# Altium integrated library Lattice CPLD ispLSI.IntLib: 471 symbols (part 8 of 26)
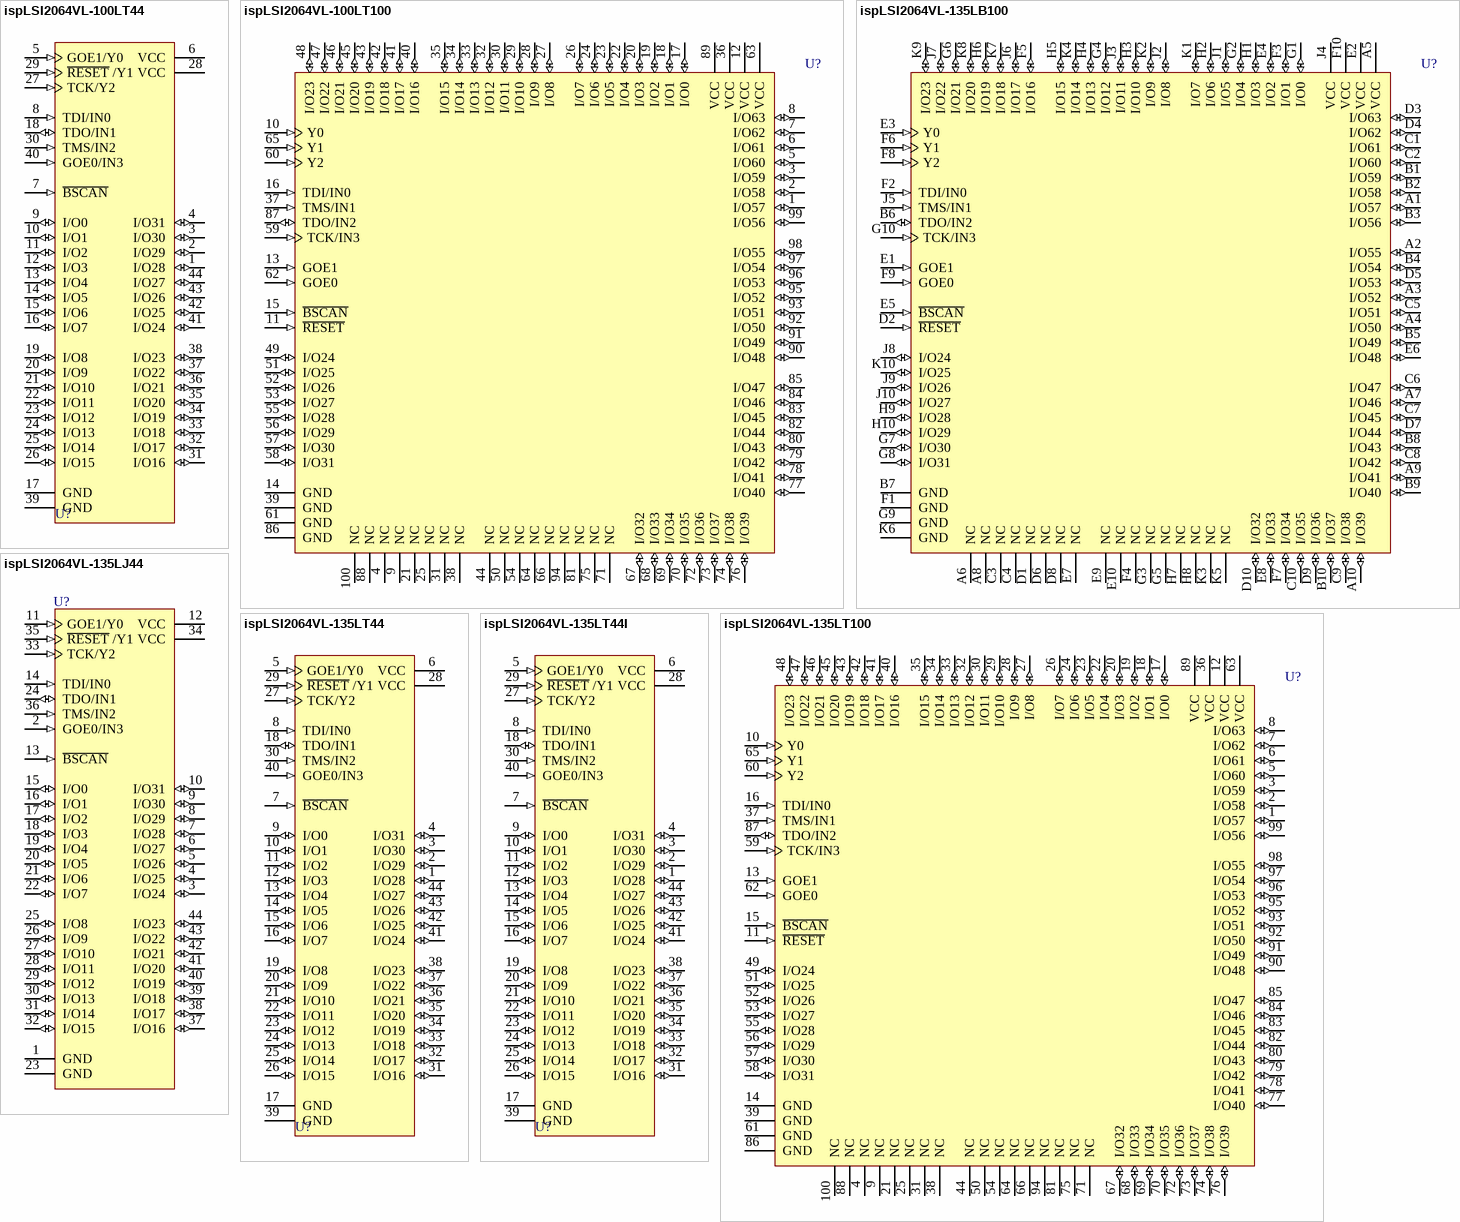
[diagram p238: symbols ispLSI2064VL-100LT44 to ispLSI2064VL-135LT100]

## ispLSI2064VL-100LT44
designator U?
2.5V In-System Programmable SuperFAST High Density PLD
footprint TQFP44_N (Thin QFP, 44-Leads, Body 10x10mm, Pitch 0.8mm, IPC Medium Density)
footprint TQFP44_L (Thin QFP, 44-Leads, Body 10x10mm, Pitch 0.8mm, IPC High Density)
footprint TQFP44_M (Thin QFP, 44-Leads, Body 10x10mm, Pitch 0.8mm, IPC Low Density)
3D model 2064VL-TQFP44 (44-Pin Thin Quad Flat Pack 0.8 mm Pitch)
pins: 1 I/O28 (io), 2 I/O29 (io), 3 I/O30 (io), 4 I/O31 (io), 5 GOE1/Y0 (in), 6 VCC (power), 7 ~{BSCAN} (in), 8 TDI/IN0 (in), 9 I/O0 (io), 10 I/O1 (io), 11 I/O2 (io), 12 I/O3 (io), 13 I/O4 (io), 14 I/O5 (io), 15 I/O6 (io), 16 I/O7 (io), 17 GND (power), 18 TDO/IN1 (io), 19 I/O8 (io), 20 I/O9 (io), 21 I/O10 (io), 22 I/O11 (io), 23 I/O12 (io), 24 I/O13 (io), 25 I/O14 (io), 26 I/O15 (io), 27 TCK/Y2 (in), 28 VCC (power), 29 ~{RESET} /Y1 (in), 30 TMS/IN2 (in), 31 I/O16 (io), 32 I/O17 (io), 33 I/O18 (io), 34 I/O19 (io), 35 I/O20 (io), 36 I/O21 (io), 37 I/O22 (io), 38 I/O23 (io), 39 GND (power), 40 GOE0/IN3 (in), 41 I/O24 (io), 42 I/O25 (io), 43 I/O26 (io), 44 I/O27 (io)

## ispLSI2064VL-100LT100
designator U?
2.5V In-System Programmable SuperFAST High Density PLD
footprint TQFP100_N (Thin QFP, 100-Leads, Body 14x14mm, Pitch 0.5mm, IPC Medium Density)
footprint TQFP100_L (Thin QFP, 100-Leads, Body 14x14mm, Pitch 0.5mm, IPC High Density)
footprint TQFP100_M (Thin QFP, 100-Leads, Body 14x14mm, Pitch 0.5mm, IPC Low Density)
3D model 2064VL-TQFP100 (100-Pin Thin Quad Flat Pack (TQFP100))
pins: 1 I/O57 (io), 2 I/O58 (io), 3 I/O59 (io), 4 NC, 5 I/O60 (io), 6 I/O61 (io), 7 I/O62 (io), 8 I/O63 (io), 9 NC, 10 Y0 (in), 11 ~{RESET} (in), 12 VCC (power), 13 GOE1 (in), 14 GND (power), 15 ~{BSCAN} (in), 16 TDI/IN0 (in), 17 I/O0 (io), 18 I/O1 (io), 19 I/O2 (io), 20 I/O3 (io), 21 NC, 22 I/O4 (io), 23 I/O5 (io), 24 I/O6 (io), 25 NC, 26 I/O7 (io), 27 I/O8 (io), 28 I/O9 (io), 29 I/O10 (io), 30 I/O11 (io), 31 NC, 32 I/O12 (io), 33 I/O13 (io), 34 I/O14 (io), 35 I/O15 (io), 36 VCC (power), 37 TMS/IN1 (in), 38 NC, 39 GND (power), 40 I/O16 (io), 41 I/O17 (io), 42 I/O18 (io), 43 I/O19 (io), 44 NC, 45 I/O20 (io), 46 I/O21 (io), 47 I/O22 (io), 48 I/O23 (io), 49 I/O24 (io), 50 NC, 51 I/O25 (io), 52 I/O26 (io), 53 I/O27 (io), 54 NC, 55 I/O28 (io), 56 I/O29 (io), 57 I/O30 (io), 58 I/O31 (io), 59 TCK/IN3 (in), 60 Y2 (in), 61 GND (power), 62 GOE0 (in), 63 VCC (power), 64 NC, 65 Y1 (in), 66 NC, 67 I/O32 (io), 68 I/O33 (io), 69 I/O34 (io), 70 I/O35 (io), 71 NC, 72 I/O36 (io), 73 I/O37 (io), 74 I/O38 (io), 75 NC, 76 I/O39 (io), 77 I/O40 (io), 78 I/O41 (io), 79 I/O42 (io), 80 I/O43 (io), 81 NC, 82 I/O44 (io), 83 I/O45 (io), 84 I/O46 (io), 85 I/O47 (io), 86 GND (power), 87 TDO/IN2 (io), 88 NC, 89 VCC (power), 90 I/O48 (io), 91 I/O49 (io), 92 I/O50 (io), 93 I/O51 (io), 94 NC, 95 I/O52 (io), 96 I/O53 (io), 97 I/O54 (io), 98 I/O55 (io), 99 I/O56 (io), 100 NC

## ispLSI2064VL-135LB100
designator U?
2.5V In-System Programmable SuperFAST High Density PLD
footprint caBGA100 (BGA, 100-Leads, Body 10x10mm, Pitch 0.8mm)
3D model 2064VL-caBGA100 (100-Ball Chip Array Ball Grid Array (caBGA100))
pins: A1 I/O57 (io), A2 I/O55 (io), A3 I/O52 (io), A4 I/O50 (io), A5 VCC (power), A6 NC, A7 I/O46 (io), A8 NC, A9 I/O41 (io), A10 I/O39 (io), B1 I/O59 (io), B2 I/O58 (io), B3 I/O56 (io), B4 I/O54 (io), B5 I/O49 (io), B6 TDO/IN2 (io), B7 GND (power), B8 I/O43 (io), B9 I/O40 (io), B10 I/O37 (io), C1 I/O61 (io), C2 I/O60 (io), C3 NC, C4 NC, C5 I/O51 (io), C6 I/O47 (io), C7 I/O45 (io), C8 I/O42 (io), C9 I/O38 (io), C10 I/O35 (io), D1 NC, D2 ~{RESET} (in), D3 I/O63 (io), D4 I/O62 (io), D5 I/O53 (io), D6 NC, D7 I/O44 (io), D8 NC, D9 I/O36 (io), D10 I/O32 (io), E1 GOE1 (in), E2 VCC (power), E3 Y0 (in), E4 I/O2 (io), E5 ~{BSCAN} (in), E6 I/O48 (io), E7 NC, E8 I/O33 (io), E9 NC, E10 NC, F1 GND (power), F2 TDI/IN0 (in), F3 I/O1 (io), F4 NC, F5 I/O16 (io), F6 Y1 (in), F7 I/O34 (io), F8 Y2 (in), F9 GOE0 (in), F10 VCC (power), G1 I/O0 (io), G2 I/O4 (io), G3 NC, G4 I/O12 (io), G5 NC, G6 I/O21 (io), G7 I/O30 (io), G8 I/O31 (io), G9 GND (power), G10 TCK/IN3 (in), H1 I/O3 (io), H2 I/O6 (io), H3 I/O10 (io), H4 I/O13 (io), H5 I/O15 (io), H6 I/O19 (io), H7 NC, H8 NC, H9 I/O28 (io), H10 I/O29 (io), J1 I/O5 (io), J2 I/O8 (io), J3 I/O11 (io), J4 VCC (power), J5 TMS/IN1 (in), J6 I/O17 (io), J7 I/O22 (io), J8 I/O24 (io), J9 I/O26 (io), J10 I/O27 (io), K1 I/O7 (io), K2 I/O9 (io), K3 NC, K4 I/O14 (io), K5 NC, K6 GND (power), K7 I/O18 (io), K8 I/O20 (io), K9 I/O23 (io), K10 I/O25 (io)

## ispLSI2064VL-135LJ44
designator U?
2.5V In-System Programmable SuperFAST High Density PLD
footprint PLCC44_N (Leaded Chip Carrier, 44-Leads, Body 16.6x16.6mm, Pitch 1.27mm, IPC Medium Density)
footprint PLCC44_L (Leaded Chip Carrier, 44-Leads, Body 16.6x16.6mm, Pitch 1.27mm, IPC High Density)
footprint PLCC44_M (Leaded Chip Carrier, 44-Leads, Body 16.6x16.6mm, Pitch 1.27mm, IPC Low Density)
3D model 2064VL-PLCC44 (44-Pin Leaded Chip Carrier 1.27 mm Pitch)
pins: 1 GND (power), 2 GOE0/IN3 (in), 3 I/O24 (io), 4 I/O25 (io), 5 I/O26 (io), 6 I/O27 (io), 7 I/O28 (io), 8 I/O29 (io), 9 I/O30 (io), 10 I/O31 (io), 11 GOE1/Y0 (in), 12 VCC (power), 13 ~{BSCAN} (in), 14 TDI/IN0 (in), 15 I/O0 (io), 16 I/O1 (io), 17 I/O2 (io), 18 I/O3 (io), 19 I/O4 (io), 20 I/O5 (io), 21 I/O6 (io), 22 I/O7 (io), 23 GND (power), 24 TDO/IN1 (io), 25 I/O8 (io), 26 I/O9 (io), 27 I/O10 (io), 28 I/O11 (io), 29 I/O12 (io), 30 I/O13 (io), 31 I/O14 (io), 32 I/O15 (io), 33 TCK/Y2 (in), 34 VCC (power), 35 ~{RESET} /Y1 (in), 36 TMS/IN2 (in), 37 I/O16 (io), 38 I/O17 (io), 39 I/O18 (io), 40 I/O19 (io), 41 I/O20 (io), 42 I/O21 (io), 43 I/O22 (io), 44 I/O23 (io)

## ispLSI2064VL-135LT44
designator U?
2.5V In-System Programmable SuperFAST High Density PLD
footprint TQFP44_N (Thin QFP, 44-Leads, Body 10x10mm, Pitch 0.8mm, IPC Medium Density)
footprint TQFP44_L (Thin QFP, 44-Leads, Body 10x10mm, Pitch 0.8mm, IPC High Density)
footprint TQFP44_M (Thin QFP, 44-Leads, Body 10x10mm, Pitch 0.8mm, IPC Low Density)
3D model 2064VL-TQFP44 (44-Pin Thin Quad Flat Pack 0.8 mm Pitch)
pins: 1 I/O28 (io), 2 I/O29 (io), 3 I/O30 (io), 4 I/O31 (io), 5 GOE1/Y0 (in), 6 VCC (power), 7 ~{BSCAN} (in), 8 TDI/IN0 (in), 9 I/O0 (io), 10 I/O1 (io), 11 I/O2 (io), 12 I/O3 (io), 13 I/O4 (io), 14 I/O5 (io), 15 I/O6 (io), 16 I/O7 (io), 17 GND (power), 18 TDO/IN1 (io), 19 I/O8 (io), 20 I/O9 (io), 21 I/O10 (io), 22 I/O11 (io), 23 I/O12 (io), 24 I/O13 (io), 25 I/O14 (io), 26 I/O15 (io), 27 TCK/Y2 (in), 28 VCC (power), 29 ~{RESET} /Y1 (in), 30 TMS/IN2 (in), 31 I/O16 (io), 32 I/O17 (io), 33 I/O18 (io), 34 I/O19 (io), 35 I/O20 (io), 36 I/O21 (io), 37 I/O22 (io), 38 I/O23 (io), 39 GND (power), 40 GOE0/IN3 (in), 41 I/O24 (io), 42 I/O25 (io), 43 I/O26 (io), 44 I/O27 (io)

## ispLSI2064VL-135LT44I
designator U?
2.5V In-System Programmable SuperFAST High Density PLD
footprint TQFP44_N (Thin QFP, 44-Leads, Body 10x10mm, Pitch 0.8mm, IPC Medium Density)
footprint TQFP44_L (Thin QFP, 44-Leads, Body 10x10mm, Pitch 0.8mm, IPC High Density)
footprint TQFP44_M (Thin QFP, 44-Leads, Body 10x10mm, Pitch 0.8mm, IPC Low Density)
3D model 2064VL-TQFP44 (44-Pin Thin Quad Flat Pack 0.8 mm Pitch)
pins: 1 I/O28 (io), 2 I/O29 (io), 3 I/O30 (io), 4 I/O31 (io), 5 GOE1/Y0 (in), 6 VCC (power), 7 ~{BSCAN} (in), 8 TDI/IN0 (in), 9 I/O0 (io), 10 I/O1 (io), 11 I/O2 (io), 12 I/O3 (io), 13 I/O4 (io), 14 I/O5 (io), 15 I/O6 (io), 16 I/O7 (io), 17 GND (power), 18 TDO/IN1 (io), 19 I/O8 (io), 20 I/O9 (io), 21 I/O10 (io), 22 I/O11 (io), 23 I/O12 (io), 24 I/O13 (io), 25 I/O14 (io), 26 I/O15 (io), 27 TCK/Y2 (in), 28 VCC (power), 29 ~{RESET} /Y1 (in), 30 TMS/IN2 (in), 31 I/O16 (io), 32 I/O17 (io), 33 I/O18 (io), 34 I/O19 (io), 35 I/O20 (io), 36 I/O21 (io), 37 I/O22 (io), 38 I/O23 (io), 39 GND (power), 40 GOE0/IN3 (in), 41 I/O24 (io), 42 I/O25 (io), 43 I/O26 (io), 44 I/O27 (io)

## ispLSI2064VL-135LT100
designator U?
2.5V In-System Programmable SuperFAST High Density PLD
footprint TQFP100_N (Thin QFP, 100-Leads, Body 14x14mm, Pitch 0.5mm, IPC Medium Density)
footprint TQFP100_L (Thin QFP, 100-Leads, Body 14x14mm, Pitch 0.5mm, IPC High Density)
footprint TQFP100_M (Thin QFP, 100-Leads, Body 14x14mm, Pitch 0.5mm, IPC Low Density)
3D model 2064VL-TQFP100 (100-Pin Thin Quad Flat Pack (TQFP100))
pins: 1 I/O57 (io), 2 I/O58 (io), 3 I/O59 (io), 4 NC, 5 I/O60 (io), 6 I/O61 (io), 7 I/O62 (io), 8 I/O63 (io), 9 NC, 10 Y0 (in), 11 ~{RESET} (in), 12 VCC (power), 13 GOE1 (in), 14 GND (power), 15 ~{BSCAN} (in), 16 TDI/IN0 (in), 17 I/O0 (io), 18 I/O1 (io), 19 I/O2 (io), 20 I/O3 (io), 21 NC, 22 I/O4 (io), 23 I/O5 (io), 24 I/O6 (io), 25 NC, 26 I/O7 (io), 27 I/O8 (io), 28 I/O9 (io), 29 I/O10 (io), 30 I/O11 (io), 31 NC, 32 I/O12 (io), 33 I/O13 (io), 34 I/O14 (io), 35 I/O15 (io), 36 VCC (power), 37 TMS/IN1 (in), 38 NC, 39 GND (power), 40 I/O16 (io), 41 I/O17 (io), 42 I/O18 (io), 43 I/O19 (io), 44 NC, 45 I/O20 (io), 46 I/O21 (io), 47 I/O22 (io), 48 I/O23 (io), 49 I/O24 (io), 50 NC, 51 I/O25 (io), 52 I/O26 (io), 53 I/O27 (io), 54 NC, 55 I/O28 (io), 56 I/O29 (io), 57 I/O30 (io), 58 I/O31 (io), 59 TCK/IN3 (in), 60 Y2 (in), 61 GND (power), 62 GOE0 (in), 63 VCC (power), 64 NC, 65 Y1 (in), 66 NC, 67 I/O32 (io), 68 I/O33 (io), 69 I/O34 (io), 70 I/O35 (io), 71 NC, 72 I/O36 (io), 73 I/O37 (io), 74 I/O38 (io), 75 NC, 76 I/O39 (io), 77 I/O40 (io), 78 I/O41 (io), 79 I/O42 (io), 80 I/O43 (io), 81 NC, 82 I/O44 (io), 83 I/O45 (io), 84 I/O46 (io), 85 I/O47 (io), 86 GND (power), 87 TDO/IN2 (io), 88 NC, 89 VCC (power), 90 I/O48 (io), 91 I/O49 (io), 92 I/O50 (io), 93 I/O51 (io), 94 NC, 95 I/O52 (io), 96 I/O53 (io), 97 I/O54 (io), 98 I/O55 (io), 99 I/O56 (io), 100 NC

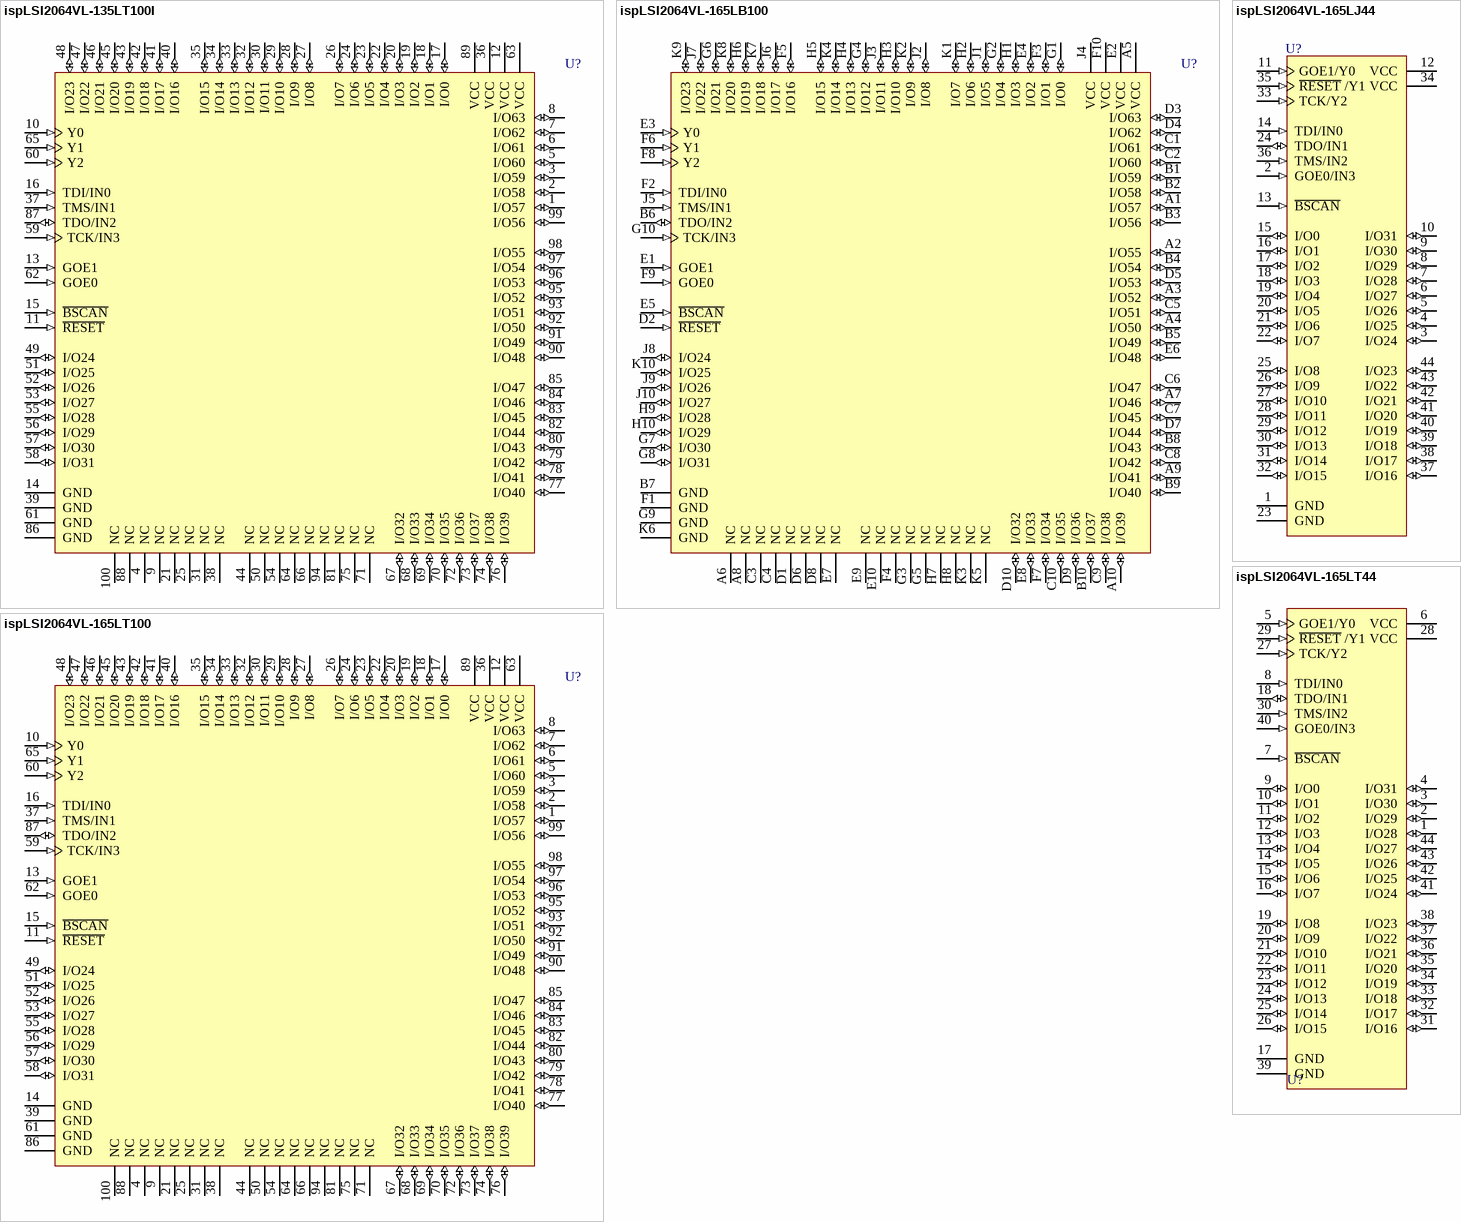
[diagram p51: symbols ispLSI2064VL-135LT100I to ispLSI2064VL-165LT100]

## ispLSI2064VL-135LT100I
designator U?
2.5V In-System Programmable SuperFAST High Density PLD
footprint TQFP100_N (Thin QFP, 100-Leads, Body 14x14mm, Pitch 0.5mm, IPC Medium Density)
footprint TQFP100_L (Thin QFP, 100-Leads, Body 14x14mm, Pitch 0.5mm, IPC High Density)
footprint TQFP100_M (Thin QFP, 100-Leads, Body 14x14mm, Pitch 0.5mm, IPC Low Density)
3D model 2064VL-TQFP100 (100-Pin Thin Quad Flat Pack (TQFP100))
pins: 1 I/O57 (io), 2 I/O58 (io), 3 I/O59 (io), 4 NC, 5 I/O60 (io), 6 I/O61 (io), 7 I/O62 (io), 8 I/O63 (io), 9 NC, 10 Y0 (in), 11 ~{RESET} (in), 12 VCC (power), 13 GOE1 (in), 14 GND (power), 15 ~{BSCAN} (in), 16 TDI/IN0 (in), 17 I/O0 (io), 18 I/O1 (io), 19 I/O2 (io), 20 I/O3 (io), 21 NC, 22 I/O4 (io), 23 I/O5 (io), 24 I/O6 (io), 25 NC, 26 I/O7 (io), 27 I/O8 (io), 28 I/O9 (io), 29 I/O10 (io), 30 I/O11 (io), 31 NC, 32 I/O12 (io), 33 I/O13 (io), 34 I/O14 (io), 35 I/O15 (io), 36 VCC (power), 37 TMS/IN1 (in), 38 NC, 39 GND (power), 40 I/O16 (io), 41 I/O17 (io), 42 I/O18 (io), 43 I/O19 (io), 44 NC, 45 I/O20 (io), 46 I/O21 (io), 47 I/O22 (io), 48 I/O23 (io), 49 I/O24 (io), 50 NC, 51 I/O25 (io), 52 I/O26 (io), 53 I/O27 (io), 54 NC, 55 I/O28 (io), 56 I/O29 (io), 57 I/O30 (io), 58 I/O31 (io), 59 TCK/IN3 (in), 60 Y2 (in), 61 GND (power), 62 GOE0 (in), 63 VCC (power), 64 NC, 65 Y1 (in), 66 NC, 67 I/O32 (io), 68 I/O33 (io), 69 I/O34 (io), 70 I/O35 (io), 71 NC, 72 I/O36 (io), 73 I/O37 (io), 74 I/O38 (io), 75 NC, 76 I/O39 (io), 77 I/O40 (io), 78 I/O41 (io), 79 I/O42 (io), 80 I/O43 (io), 81 NC, 82 I/O44 (io), 83 I/O45 (io), 84 I/O46 (io), 85 I/O47 (io), 86 GND (power), 87 TDO/IN2 (io), 88 NC, 89 VCC (power), 90 I/O48 (io), 91 I/O49 (io), 92 I/O50 (io), 93 I/O51 (io), 94 NC, 95 I/O52 (io), 96 I/O53 (io), 97 I/O54 (io), 98 I/O55 (io), 99 I/O56 (io), 100 NC

## ispLSI2064VL-165LB100
designator U?
2.5V In-System Programmable SuperFAST High Density PLD
footprint caBGA100 (BGA, 100-Leads, Body 10x10mm, Pitch 0.8mm)
3D model 2064VL-caBGA100 (100-Ball Chip Array Ball Grid Array (caBGA100))
pins: A1 I/O57 (io), A2 I/O55 (io), A3 I/O52 (io), A4 I/O50 (io), A5 VCC (power), A6 NC, A7 I/O46 (io), A8 NC, A9 I/O41 (io), A10 I/O39 (io), B1 I/O59 (io), B2 I/O58 (io), B3 I/O56 (io), B4 I/O54 (io), B5 I/O49 (io), B6 TDO/IN2 (io), B7 GND (power), B8 I/O43 (io), B9 I/O40 (io), B10 I/O37 (io), C1 I/O61 (io), C2 I/O60 (io), C3 NC, C4 NC, C5 I/O51 (io), C6 I/O47 (io), C7 I/O45 (io), C8 I/O42 (io), C9 I/O38 (io), C10 I/O35 (io), D1 NC, D2 ~{RESET} (in), D3 I/O63 (io), D4 I/O62 (io), D5 I/O53 (io), D6 NC, D7 I/O44 (io), D8 NC, D9 I/O36 (io), D10 I/O32 (io), E1 GOE1 (in), E2 VCC (power), E3 Y0 (in), E4 I/O2 (io), E5 ~{BSCAN} (in), E6 I/O48 (io), E7 NC, E8 I/O33 (io), E9 NC, E10 NC, F1 GND (power), F2 TDI/IN0 (in), F3 I/O1 (io), F4 NC, F5 I/O16 (io), F6 Y1 (in), F7 I/O34 (io), F8 Y2 (in), F9 GOE0 (in), F10 VCC (power), G1 I/O0 (io), G2 I/O4 (io), G3 NC, G4 I/O12 (io), G5 NC, G6 I/O21 (io), G7 I/O30 (io), G8 I/O31 (io), G9 GND (power), G10 TCK/IN3 (in), H1 I/O3 (io), H2 I/O6 (io), H3 I/O10 (io), H4 I/O13 (io), H5 I/O15 (io), H6 I/O19 (io), H7 NC, H8 NC, H9 I/O28 (io), H10 I/O29 (io), J1 I/O5 (io), J2 I/O8 (io), J3 I/O11 (io), J4 VCC (power), J5 TMS/IN1 (in), J6 I/O17 (io), J7 I/O22 (io), J8 I/O24 (io), J9 I/O26 (io), J10 I/O27 (io), K1 I/O7 (io), K2 I/O9 (io), K3 NC, K4 I/O14 (io), K5 NC, K6 GND (power), K7 I/O18 (io), K8 I/O20 (io), K9 I/O23 (io), K10 I/O25 (io)

## ispLSI2064VL-165LJ44
designator U?
2.5V In-System Programmable SuperFAST High Density PLD
footprint PLCC44_N (Leaded Chip Carrier, 44-Leads, Body 16.6x16.6mm, Pitch 1.27mm, IPC Medium Density)
footprint PLCC44_L (Leaded Chip Carrier, 44-Leads, Body 16.6x16.6mm, Pitch 1.27mm, IPC High Density)
footprint PLCC44_M (Leaded Chip Carrier, 44-Leads, Body 16.6x16.6mm, Pitch 1.27mm, IPC Low Density)
3D model 2064VL-PLCC44 (44-Pin Leaded Chip Carrier 1.27 mm Pitch)
pins: 1 GND (power), 2 GOE0/IN3 (in), 3 I/O24 (io), 4 I/O25 (io), 5 I/O26 (io), 6 I/O27 (io), 7 I/O28 (io), 8 I/O29 (io), 9 I/O30 (io), 10 I/O31 (io), 11 GOE1/Y0 (in), 12 VCC (power), 13 ~{BSCAN} (in), 14 TDI/IN0 (in), 15 I/O0 (io), 16 I/O1 (io), 17 I/O2 (io), 18 I/O3 (io), 19 I/O4 (io), 20 I/O5 (io), 21 I/O6 (io), 22 I/O7 (io), 23 GND (power), 24 TDO/IN1 (io), 25 I/O8 (io), 26 I/O9 (io), 27 I/O10 (io), 28 I/O11 (io), 29 I/O12 (io), 30 I/O13 (io), 31 I/O14 (io), 32 I/O15 (io), 33 TCK/Y2 (in), 34 VCC (power), 35 ~{RESET} /Y1 (in), 36 TMS/IN2 (in), 37 I/O16 (io), 38 I/O17 (io), 39 I/O18 (io), 40 I/O19 (io), 41 I/O20 (io), 42 I/O21 (io), 43 I/O22 (io), 44 I/O23 (io)

## ispLSI2064VL-165LT44
designator U?
2.5V In-System Programmable SuperFAST High Density PLD
footprint TQFP44_N (Thin QFP, 44-Leads, Body 10x10mm, Pitch 0.8mm, IPC Medium Density)
footprint TQFP44_L (Thin QFP, 44-Leads, Body 10x10mm, Pitch 0.8mm, IPC High Density)
footprint TQFP44_M (Thin QFP, 44-Leads, Body 10x10mm, Pitch 0.8mm, IPC Low Density)
3D model 2064VL-TQFP44 (44-Pin Thin Quad Flat Pack 0.8 mm Pitch)
pins: 1 I/O28 (io), 2 I/O29 (io), 3 I/O30 (io), 4 I/O31 (io), 5 GOE1/Y0 (in), 6 VCC (power), 7 ~{BSCAN} (in), 8 TDI/IN0 (in), 9 I/O0 (io), 10 I/O1 (io), 11 I/O2 (io), 12 I/O3 (io), 13 I/O4 (io), 14 I/O5 (io), 15 I/O6 (io), 16 I/O7 (io), 17 GND (power), 18 TDO/IN1 (io), 19 I/O8 (io), 20 I/O9 (io), 21 I/O10 (io), 22 I/O11 (io), 23 I/O12 (io), 24 I/O13 (io), 25 I/O14 (io), 26 I/O15 (io), 27 TCK/Y2 (in), 28 VCC (power), 29 ~{RESET} /Y1 (in), 30 TMS/IN2 (in), 31 I/O16 (io), 32 I/O17 (io), 33 I/O18 (io), 34 I/O19 (io), 35 I/O20 (io), 36 I/O21 (io), 37 I/O22 (io), 38 I/O23 (io), 39 GND (power), 40 GOE0/IN3 (in), 41 I/O24 (io), 42 I/O25 (io), 43 I/O26 (io), 44 I/O27 (io)

## ispLSI2064VL-165LT100
designator U?
2.5V In-System Programmable SuperFAST High Density PLD
footprint TQFP100_N (Thin QFP, 100-Leads, Body 14x14mm, Pitch 0.5mm, IPC Medium Density)
footprint TQFP100_L (Thin QFP, 100-Leads, Body 14x14mm, Pitch 0.5mm, IPC High Density)
footprint TQFP100_M (Thin QFP, 100-Leads, Body 14x14mm, Pitch 0.5mm, IPC Low Density)
3D model 2064VL-TQFP100 (100-Pin Thin Quad Flat Pack (TQFP100))
pins: 1 I/O57 (io), 2 I/O58 (io), 3 I/O59 (io), 4 NC, 5 I/O60 (io), 6 I/O61 (io), 7 I/O62 (io), 8 I/O63 (io), 9 NC, 10 Y0 (in), 11 ~{RESET} (in), 12 VCC (power), 13 GOE1 (in), 14 GND (power), 15 ~{BSCAN} (in), 16 TDI/IN0 (in), 17 I/O0 (io), 18 I/O1 (io), 19 I/O2 (io), 20 I/O3 (io), 21 NC, 22 I/O4 (io), 23 I/O5 (io), 24 I/O6 (io), 25 NC, 26 I/O7 (io), 27 I/O8 (io), 28 I/O9 (io), 29 I/O10 (io), 30 I/O11 (io), 31 NC, 32 I/O12 (io), 33 I/O13 (io), 34 I/O14 (io), 35 I/O15 (io), 36 VCC (power), 37 TMS/IN1 (in), 38 NC, 39 GND (power), 40 I/O16 (io), 41 I/O17 (io), 42 I/O18 (io), 43 I/O19 (io), 44 NC, 45 I/O20 (io), 46 I/O21 (io), 47 I/O22 (io), 48 I/O23 (io), 49 I/O24 (io), 50 NC, 51 I/O25 (io), 52 I/O26 (io), 53 I/O27 (io), 54 NC, 55 I/O28 (io), 56 I/O29 (io), 57 I/O30 (io), 58 I/O31 (io), 59 TCK/IN3 (in), 60 Y2 (in), 61 GND (power), 62 GOE0 (in), 63 VCC (power), 64 NC, 65 Y1 (in), 66 NC, 67 I/O32 (io), 68 I/O33 (io), 69 I/O34 (io), 70 I/O35 (io), 71 NC, 72 I/O36 (io), 73 I/O37 (io), 74 I/O38 (io), 75 NC, 76 I/O39 (io), 77 I/O40 (io), 78 I/O41 (io), 79 I/O42 (io), 80 I/O43 (io), 81 NC, 82 I/O44 (io), 83 I/O45 (io), 84 I/O46 (io), 85 I/O47 (io), 86 GND (power), 87 TDO/IN2 (io), 88 NC, 89 VCC (power), 90 I/O48 (io), 91 I/O49 (io), 92 I/O50 (io), 93 I/O51 (io), 94 NC, 95 I/O52 (io), 96 I/O53 (io), 97 I/O54 (io), 98 I/O55 (io), 99 I/O56 (io), 100 NC

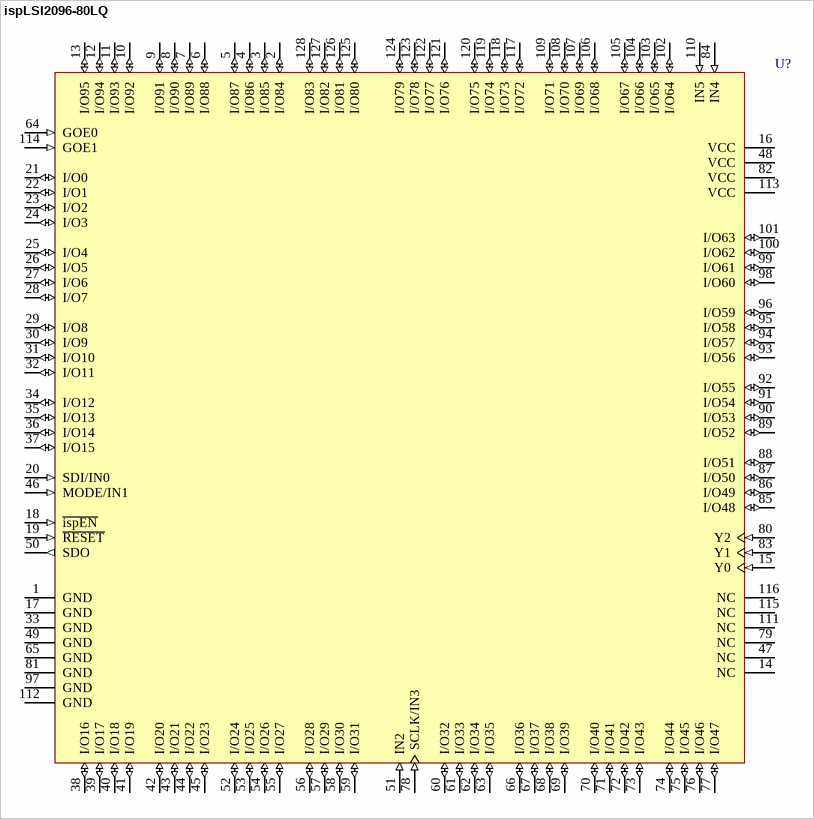
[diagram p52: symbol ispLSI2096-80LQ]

## ispLSI2096-80LQ
designator U?
In-System Programmable High-Density PLD; Note: Pins 20, 46 and 78 have dual function capability.
footprint PQFP128_N (QFP, 128-Leads, Body 28x28mm, Pitch 0.8mm, IPC Medium Density)
footprint PQFP128_L (QFP, 128-Leads, Body 28x28mm, Pitch 0.8mm, IPC High Density)
footprint PQFP128_M (QFP, 128-Leads, Body 28x28mm, Pitch 0.8mm, IPC Low Density)
3D model 2096-PQFP128 (128-Pin Quad Flat Pack 0.8 mm Pitch)
pins: 1 GND (power), 2 I/O84 (io), 3 I/O85 (io), 4 I/O86 (io), 5 I/O87 (io), 6 I/O88 (io), 7 I/O89 (io), 8 I/O90 (io), 9 I/O91 (io), 10 I/O92 (io), 11 I/O93 (io), 12 I/O94 (io), 13 I/O95 (io), 14 NC, 15 Y0 (in), 16 VCC (power), 17 GND (power), 18 ~{ispEN} (in), 19 ~{RESET} (in), 20 SDI/IN0 (in), 21 I/O0 (io), 22 I/O1 (io), 23 I/O2 (io), 24 I/O3 (io), 25 I/O4 (io), 26 I/O5 (io), 27 I/O6 (io), 28 I/O7 (io), 29 I/O8 (io), 30 I/O9 (io), 31 I/O10 (io), 32 I/O11 (io), 33 GND (power), 34 I/O12 (io), 35 I/O13 (io), 36 I/O14 (io), 37 I/O15 (io), 38 I/O16 (io), 39 I/O17 (io), 40 I/O18 (io), 41 I/O19 (io), 42 I/O20 (io), 43 I/O21 (io), 44 I/O22 (io), 45 I/O23 (io), 46 MODE/IN1 (in), 47 NC, 48 VCC (power), 49 GND (power), 50 SDO (out), 51 IN2 (in), 52 I/O24 (io), 53 I/O25 (io), 54 I/O26 (io), 55 I/O27 (io), 56 I/O28 (io), 57 I/O29 (io), 58 I/O30 (io), 59 I/O31 (io), 60 I/O32 (io), 61 I/O33 (io), 62 I/O34 (io), 63 I/O35 (io), 64 GOE0 (in), 65 GND (power), 66 I/O36 (io), 67 I/O37 (io), 68 I/O38 (io), 69 I/O39 (io), 70 I/O40 (io), 71 I/O41 (io), 72 I/O42 (io), 73 I/O43 (io), 74 I/O44 (io), 75 I/O45 (io), 76 I/O46 (io), 77 I/O47 (io), 78 SCLK/IN3 (in), 79 NC, 80 Y2 (in), 81 GND (power), 82 VCC (power), 83 Y1 (in), 84 IN4 (in), 85 I/O48 (io), 86 I/O49 (io), 87 I/O50 (io), 88 I/O51 (io), 89 I/O52 (io), 90 I/O53 (io), 91 I/O54 (io), 92 I/O55 (io), 93 I/O56 (io), 94 I/O57 (io), 95 I/O58 (io), 96 I/O59 (io), 97 GND (power), 98 I/O60 (io), 99 I/O61 (io), 100 I/O62 (io), 101 I/O63 (io), 102 I/O64 (io), 103 I/O65 (io), 104 I/O66 (io), 105 I/O67 (io), 106 I/O68 (io), 107 I/O69 (io), 108 I/O70 (io), 109 I/O71 (io), 110 IN5 (in), 111 NC, 112 GND (power), 113 VCC (power), 114 GOE1 (in), 115 NC, 116 NC, 117 I/O72 (io), 118 I/O73 (io), 119 I/O74 (io), 120 I/O75 (io), 121 I/O76 (io), 122 I/O77 (io), 123 I/O78 (io), 124 I/O79 (io), 125 I/O80 (io), 126 I/O81 (io), 127 I/O82 (io), 128 I/O83 (io)

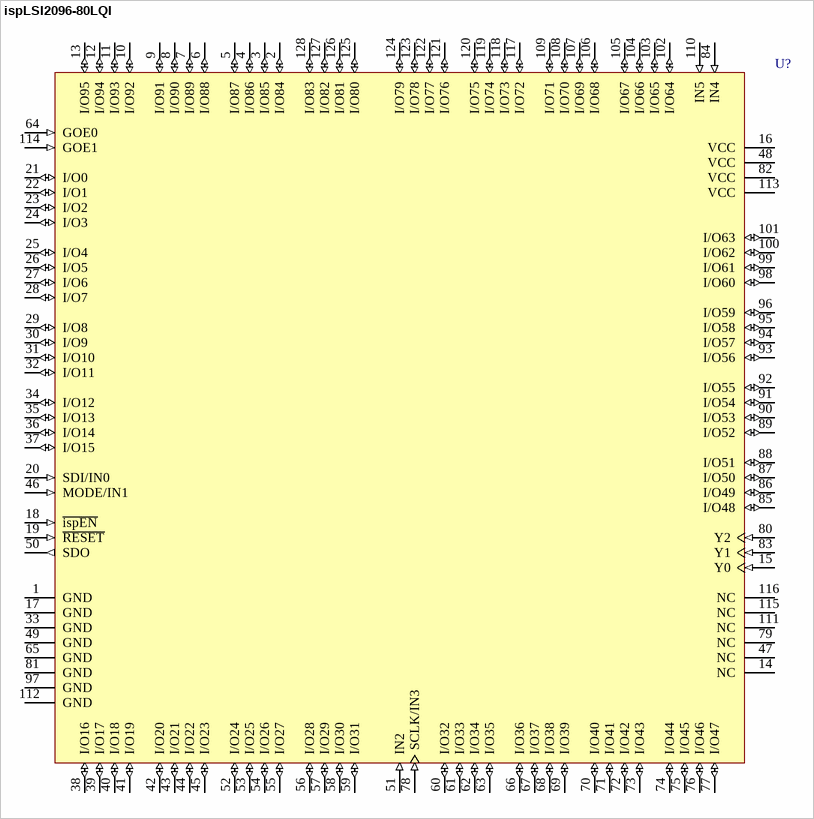
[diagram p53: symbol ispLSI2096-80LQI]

## ispLSI2096-80LQI
designator U?
In-System Programmable High-Density PLD; Note: Pins 20, 46 and 78 have dual function capability.
footprint PQFP128_N (QFP, 128-Leads, Body 28x28mm, Pitch 0.8mm, IPC Medium Density)
footprint PQFP128_L (QFP, 128-Leads, Body 28x28mm, Pitch 0.8mm, IPC High Density)
footprint PQFP128_M (QFP, 128-Leads, Body 28x28mm, Pitch 0.8mm, IPC Low Density)
3D model 2096-PQFP128 (128-Pin Quad Flat Pack 0.8 mm Pitch)
pins: 1 GND (power), 2 I/O84 (io), 3 I/O85 (io), 4 I/O86 (io), 5 I/O87 (io), 6 I/O88 (io), 7 I/O89 (io), 8 I/O90 (io), 9 I/O91 (io), 10 I/O92 (io), 11 I/O93 (io), 12 I/O94 (io), 13 I/O95 (io), 14 NC, 15 Y0 (in), 16 VCC (power), 17 GND (power), 18 ~{ispEN} (in), 19 ~{RESET} (in), 20 SDI/IN0 (in), 21 I/O0 (io), 22 I/O1 (io), 23 I/O2 (io), 24 I/O3 (io), 25 I/O4 (io), 26 I/O5 (io), 27 I/O6 (io), 28 I/O7 (io), 29 I/O8 (io), 30 I/O9 (io), 31 I/O10 (io), 32 I/O11 (io), 33 GND (power), 34 I/O12 (io), 35 I/O13 (io), 36 I/O14 (io), 37 I/O15 (io), 38 I/O16 (io), 39 I/O17 (io), 40 I/O18 (io), 41 I/O19 (io), 42 I/O20 (io), 43 I/O21 (io), 44 I/O22 (io), 45 I/O23 (io), 46 MODE/IN1 (in), 47 NC, 48 VCC (power), 49 GND (power), 50 SDO (out), 51 IN2 (in), 52 I/O24 (io), 53 I/O25 (io), 54 I/O26 (io), 55 I/O27 (io), 56 I/O28 (io), 57 I/O29 (io), 58 I/O30 (io), 59 I/O31 (io), 60 I/O32 (io), 61 I/O33 (io), 62 I/O34 (io), 63 I/O35 (io), 64 GOE0 (in), 65 GND (power), 66 I/O36 (io), 67 I/O37 (io), 68 I/O38 (io), 69 I/O39 (io), 70 I/O40 (io), 71 I/O41 (io), 72 I/O42 (io), 73 I/O43 (io), 74 I/O44 (io), 75 I/O45 (io), 76 I/O46 (io), 77 I/O47 (io), 78 SCLK/IN3 (in), 79 NC, 80 Y2 (in), 81 GND (power), 82 VCC (power), 83 Y1 (in), 84 IN4 (in), 85 I/O48 (io), 86 I/O49 (io), 87 I/O50 (io), 88 I/O51 (io), 89 I/O52 (io), 90 I/O53 (io), 91 I/O54 (io), 92 I/O55 (io), 93 I/O56 (io), 94 I/O57 (io), 95 I/O58 (io), 96 I/O59 (io), 97 GND (power), 98 I/O60 (io), 99 I/O61 (io), 100 I/O62 (io), 101 I/O63 (io), 102 I/O64 (io), 103 I/O65 (io), 104 I/O66 (io), 105 I/O67 (io), 106 I/O68 (io), 107 I/O69 (io), 108 I/O70 (io), 109 I/O71 (io), 110 IN5 (in), 111 NC, 112 GND (power), 113 VCC (power), 114 GOE1 (in), 115 NC, 116 NC, 117 I/O72 (io), 118 I/O73 (io), 119 I/O74 (io), 120 I/O75 (io), 121 I/O76 (io), 122 I/O77 (io), 123 I/O78 (io), 124 I/O79 (io), 125 I/O80 (io), 126 I/O81 (io), 127 I/O82 (io), 128 I/O83 (io)

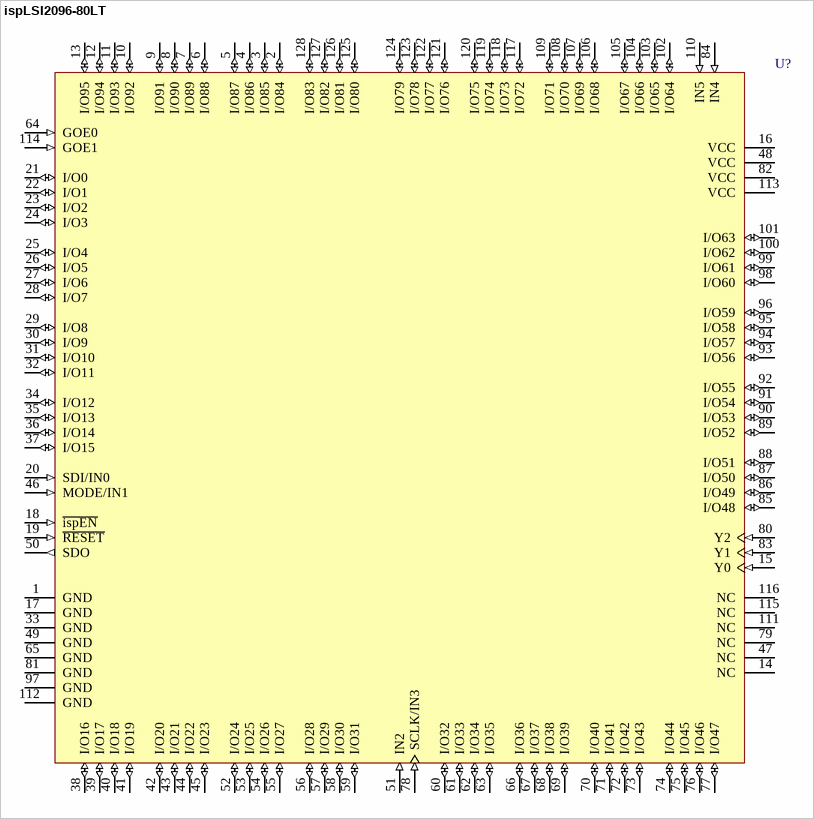
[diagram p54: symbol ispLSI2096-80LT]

## ispLSI2096-80LT
designator U?
In-System Programmable High-Density PLD; Note: Pins 20, 46 and 78 have dual function capability.
footprint TQFP128_N (Thin QFP, 128-Leads, Body 14x14mm, Pitch 0.4mm, IPC Medium Density)
footprint TQFP128_L (Thin QFP, 128-Leads, Body 14x14mm, Pitch 0.4mm, IPC High Density)
footprint TQFP128_M (Thin QFP, 128-Leads, Body 14x14mm, Pitch 0.4mm, IPC Low Density)
3D model 2096-TQFP128 (128-Pin Thin Quad Flat Pack 0.4 mm Pitch)
pins: 1 GND (power), 2 I/O84 (io), 3 I/O85 (io), 4 I/O86 (io), 5 I/O87 (io), 6 I/O88 (io), 7 I/O89 (io), 8 I/O90 (io), 9 I/O91 (io), 10 I/O92 (io), 11 I/O93 (io), 12 I/O94 (io), 13 I/O95 (io), 14 NC, 15 Y0 (in), 16 VCC (power), 17 GND (power), 18 ~{ispEN} (in), 19 ~{RESET} (in), 20 SDI/IN0 (in), 21 I/O0 (io), 22 I/O1 (io), 23 I/O2 (io), 24 I/O3 (io), 25 I/O4 (io), 26 I/O5 (io), 27 I/O6 (io), 28 I/O7 (io), 29 I/O8 (io), 30 I/O9 (io), 31 I/O10 (io), 32 I/O11 (io), 33 GND (power), 34 I/O12 (io), 35 I/O13 (io), 36 I/O14 (io), 37 I/O15 (io), 38 I/O16 (io), 39 I/O17 (io), 40 I/O18 (io), 41 I/O19 (io), 42 I/O20 (io), 43 I/O21 (io), 44 I/O22 (io), 45 I/O23 (io), 46 MODE/IN1 (in), 47 NC, 48 VCC (power), 49 GND (power), 50 SDO (out), 51 IN2 (in), 52 I/O24 (io), 53 I/O25 (io), 54 I/O26 (io), 55 I/O27 (io), 56 I/O28 (io), 57 I/O29 (io), 58 I/O30 (io), 59 I/O31 (io), 60 I/O32 (io), 61 I/O33 (io), 62 I/O34 (io), 63 I/O35 (io), 64 GOE0 (in), 65 GND (power), 66 I/O36 (io), 67 I/O37 (io), 68 I/O38 (io), 69 I/O39 (io), 70 I/O40 (io), 71 I/O41 (io), 72 I/O42 (io), 73 I/O43 (io), 74 I/O44 (io), 75 I/O45 (io), 76 I/O46 (io), 77 I/O47 (io), 78 SCLK/IN3 (in), 79 NC, 80 Y2 (in), 81 GND (power), 82 VCC (power), 83 Y1 (in), 84 IN4 (in), 85 I/O48 (io), 86 I/O49 (io), 87 I/O50 (io), 88 I/O51 (io), 89 I/O52 (io), 90 I/O53 (io), 91 I/O54 (io), 92 I/O55 (io), 93 I/O56 (io), 94 I/O57 (io), 95 I/O58 (io), 96 I/O59 (io), 97 GND (power), 98 I/O60 (io), 99 I/O61 (io), 100 I/O62 (io), 101 I/O63 (io), 102 I/O64 (io), 103 I/O65 (io), 104 I/O66 (io), 105 I/O67 (io), 106 I/O68 (io), 107 I/O69 (io), 108 I/O70 (io), 109 I/O71 (io), 110 IN5 (in), 111 NC, 112 GND (power), 113 VCC (power), 114 GOE1 (in), 115 NC, 116 NC, 117 I/O72 (io), 118 I/O73 (io), 119 I/O74 (io), 120 I/O75 (io), 121 I/O76 (io), 122 I/O77 (io), 123 I/O78 (io), 124 I/O79 (io), 125 I/O80 (io), 126 I/O81 (io), 127 I/O82 (io), 128 I/O83 (io)

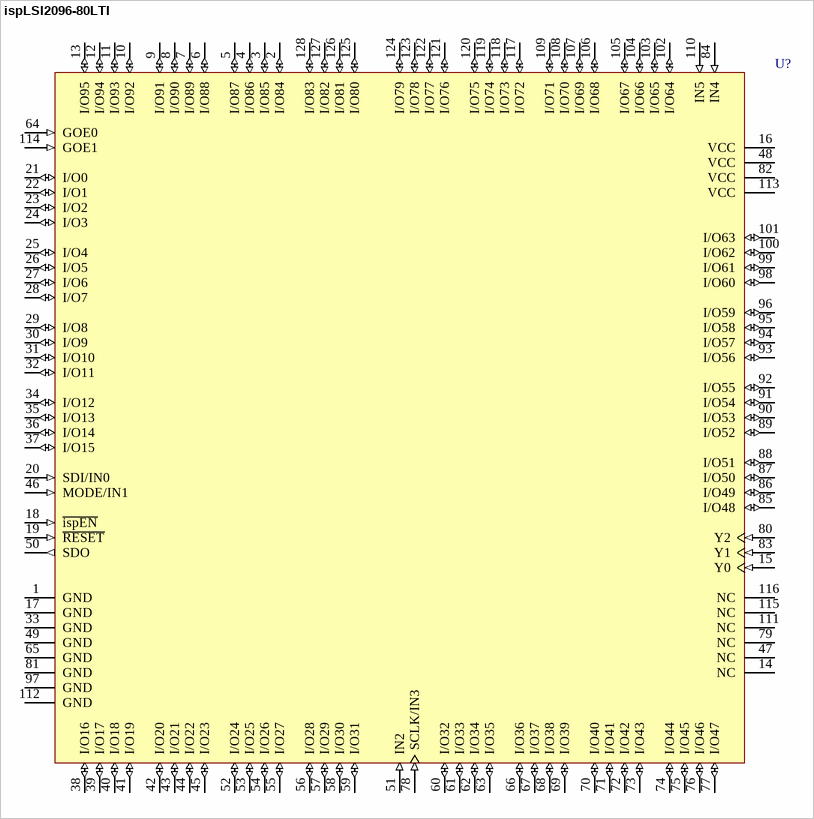
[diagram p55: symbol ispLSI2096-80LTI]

## ispLSI2096-80LTI
designator U?
In-System Programmable High-Density PLD; Note: Pins 20, 46 and 78 have dual function capability.
footprint TQFP128_N (Thin QFP, 128-Leads, Body 14x14mm, Pitch 0.4mm, IPC Medium Density)
footprint TQFP128_L (Thin QFP, 128-Leads, Body 14x14mm, Pitch 0.4mm, IPC High Density)
footprint TQFP128_M (Thin QFP, 128-Leads, Body 14x14mm, Pitch 0.4mm, IPC Low Density)
3D model 2096-TQFP128 (128-Pin Thin Quad Flat Pack 0.4 mm Pitch)
pins: 1 GND (power), 2 I/O84 (io), 3 I/O85 (io), 4 I/O86 (io), 5 I/O87 (io), 6 I/O88 (io), 7 I/O89 (io), 8 I/O90 (io), 9 I/O91 (io), 10 I/O92 (io), 11 I/O93 (io), 12 I/O94 (io), 13 I/O95 (io), 14 NC, 15 Y0 (in), 16 VCC (power), 17 GND (power), 18 ~{ispEN} (in), 19 ~{RESET} (in), 20 SDI/IN0 (in), 21 I/O0 (io), 22 I/O1 (io), 23 I/O2 (io), 24 I/O3 (io), 25 I/O4 (io), 26 I/O5 (io), 27 I/O6 (io), 28 I/O7 (io), 29 I/O8 (io), 30 I/O9 (io), 31 I/O10 (io), 32 I/O11 (io), 33 GND (power), 34 I/O12 (io), 35 I/O13 (io), 36 I/O14 (io), 37 I/O15 (io), 38 I/O16 (io), 39 I/O17 (io), 40 I/O18 (io), 41 I/O19 (io), 42 I/O20 (io), 43 I/O21 (io), 44 I/O22 (io), 45 I/O23 (io), 46 MODE/IN1 (in), 47 NC, 48 VCC (power), 49 GND (power), 50 SDO (out), 51 IN2 (in), 52 I/O24 (io), 53 I/O25 (io), 54 I/O26 (io), 55 I/O27 (io), 56 I/O28 (io), 57 I/O29 (io), 58 I/O30 (io), 59 I/O31 (io), 60 I/O32 (io), 61 I/O33 (io), 62 I/O34 (io), 63 I/O35 (io), 64 GOE0 (in), 65 GND (power), 66 I/O36 (io), 67 I/O37 (io), 68 I/O38 (io), 69 I/O39 (io), 70 I/O40 (io), 71 I/O41 (io), 72 I/O42 (io), 73 I/O43 (io), 74 I/O44 (io), 75 I/O45 (io), 76 I/O46 (io), 77 I/O47 (io), 78 SCLK/IN3 (in), 79 NC, 80 Y2 (in), 81 GND (power), 82 VCC (power), 83 Y1 (in), 84 IN4 (in), 85 I/O48 (io), 86 I/O49 (io), 87 I/O50 (io), 88 I/O51 (io), 89 I/O52 (io), 90 I/O53 (io), 91 I/O54 (io), 92 I/O55 (io), 93 I/O56 (io), 94 I/O57 (io), 95 I/O58 (io), 96 I/O59 (io), 97 GND (power), 98 I/O60 (io), 99 I/O61 (io), 100 I/O62 (io), 101 I/O63 (io), 102 I/O64 (io), 103 I/O65 (io), 104 I/O66 (io), 105 I/O67 (io), 106 I/O68 (io), 107 I/O69 (io), 108 I/O70 (io), 109 I/O71 (io), 110 IN5 (in), 111 NC, 112 GND (power), 113 VCC (power), 114 GOE1 (in), 115 NC, 116 NC, 117 I/O72 (io), 118 I/O73 (io), 119 I/O74 (io), 120 I/O75 (io), 121 I/O76 (io), 122 I/O77 (io), 123 I/O78 (io), 124 I/O79 (io), 125 I/O80 (io), 126 I/O81 (io), 127 I/O82 (io), 128 I/O83 (io)

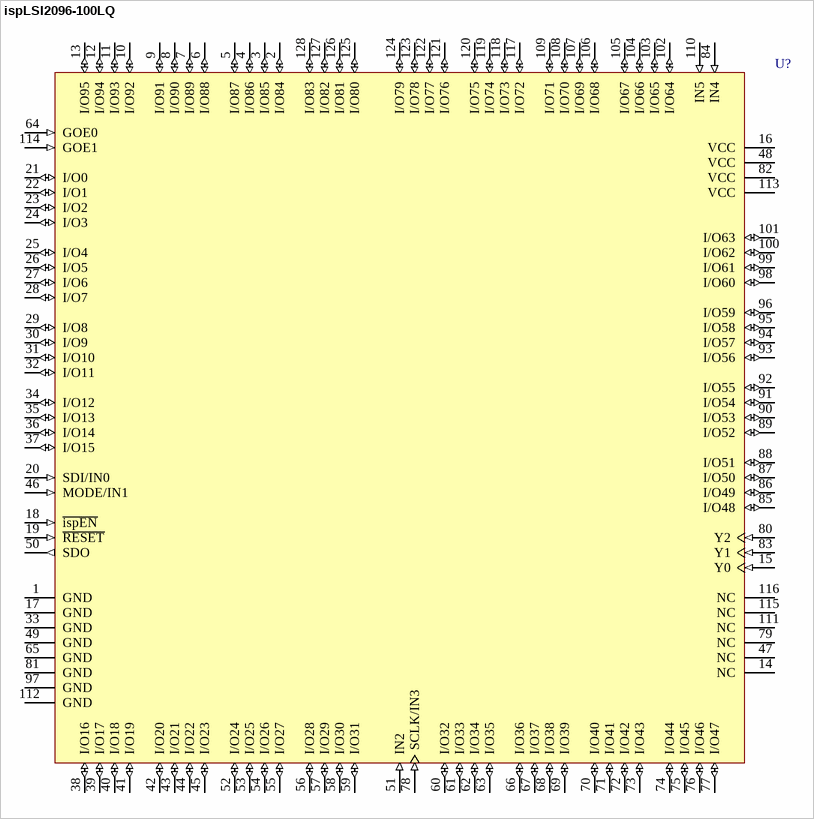
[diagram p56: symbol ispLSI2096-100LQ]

## ispLSI2096-100LQ
designator U?
In-System Programmable High-Density PLD; Note: Pins 20, 46 and 78 have dual function capability.
footprint PQFP128_N (QFP, 128-Leads, Body 28x28mm, Pitch 0.8mm, IPC Medium Density)
footprint PQFP128_L (QFP, 128-Leads, Body 28x28mm, Pitch 0.8mm, IPC High Density)
footprint PQFP128_M (QFP, 128-Leads, Body 28x28mm, Pitch 0.8mm, IPC Low Density)
3D model 2096-PQFP128 (128-Pin Quad Flat Pack 0.8 mm Pitch)
pins: 1 GND (power), 2 I/O84 (io), 3 I/O85 (io), 4 I/O86 (io), 5 I/O87 (io), 6 I/O88 (io), 7 I/O89 (io), 8 I/O90 (io), 9 I/O91 (io), 10 I/O92 (io), 11 I/O93 (io), 12 I/O94 (io), 13 I/O95 (io), 14 NC, 15 Y0 (in), 16 VCC (power), 17 GND (power), 18 ~{ispEN} (in), 19 ~{RESET} (in), 20 SDI/IN0 (in), 21 I/O0 (io), 22 I/O1 (io), 23 I/O2 (io), 24 I/O3 (io), 25 I/O4 (io), 26 I/O5 (io), 27 I/O6 (io), 28 I/O7 (io), 29 I/O8 (io), 30 I/O9 (io), 31 I/O10 (io), 32 I/O11 (io), 33 GND (power), 34 I/O12 (io), 35 I/O13 (io), 36 I/O14 (io), 37 I/O15 (io), 38 I/O16 (io), 39 I/O17 (io), 40 I/O18 (io), 41 I/O19 (io), 42 I/O20 (io), 43 I/O21 (io), 44 I/O22 (io), 45 I/O23 (io), 46 MODE/IN1 (in), 47 NC, 48 VCC (power), 49 GND (power), 50 SDO (out), 51 IN2 (in), 52 I/O24 (io), 53 I/O25 (io), 54 I/O26 (io), 55 I/O27 (io), 56 I/O28 (io), 57 I/O29 (io), 58 I/O30 (io), 59 I/O31 (io), 60 I/O32 (io), 61 I/O33 (io), 62 I/O34 (io), 63 I/O35 (io), 64 GOE0 (in), 65 GND (power), 66 I/O36 (io), 67 I/O37 (io), 68 I/O38 (io), 69 I/O39 (io), 70 I/O40 (io), 71 I/O41 (io), 72 I/O42 (io), 73 I/O43 (io), 74 I/O44 (io), 75 I/O45 (io), 76 I/O46 (io), 77 I/O47 (io), 78 SCLK/IN3 (in), 79 NC, 80 Y2 (in), 81 GND (power), 82 VCC (power), 83 Y1 (in), 84 IN4 (in), 85 I/O48 (io), 86 I/O49 (io), 87 I/O50 (io), 88 I/O51 (io), 89 I/O52 (io), 90 I/O53 (io), 91 I/O54 (io), 92 I/O55 (io), 93 I/O56 (io), 94 I/O57 (io), 95 I/O58 (io), 96 I/O59 (io), 97 GND (power), 98 I/O60 (io), 99 I/O61 (io), 100 I/O62 (io), 101 I/O63 (io), 102 I/O64 (io), 103 I/O65 (io), 104 I/O66 (io), 105 I/O67 (io), 106 I/O68 (io), 107 I/O69 (io), 108 I/O70 (io), 109 I/O71 (io), 110 IN5 (in), 111 NC, 112 GND (power), 113 VCC (power), 114 GOE1 (in), 115 NC, 116 NC, 117 I/O72 (io), 118 I/O73 (io), 119 I/O74 (io), 120 I/O75 (io), 121 I/O76 (io), 122 I/O77 (io), 123 I/O78 (io), 124 I/O79 (io), 125 I/O80 (io), 126 I/O81 (io), 127 I/O82 (io), 128 I/O83 (io)

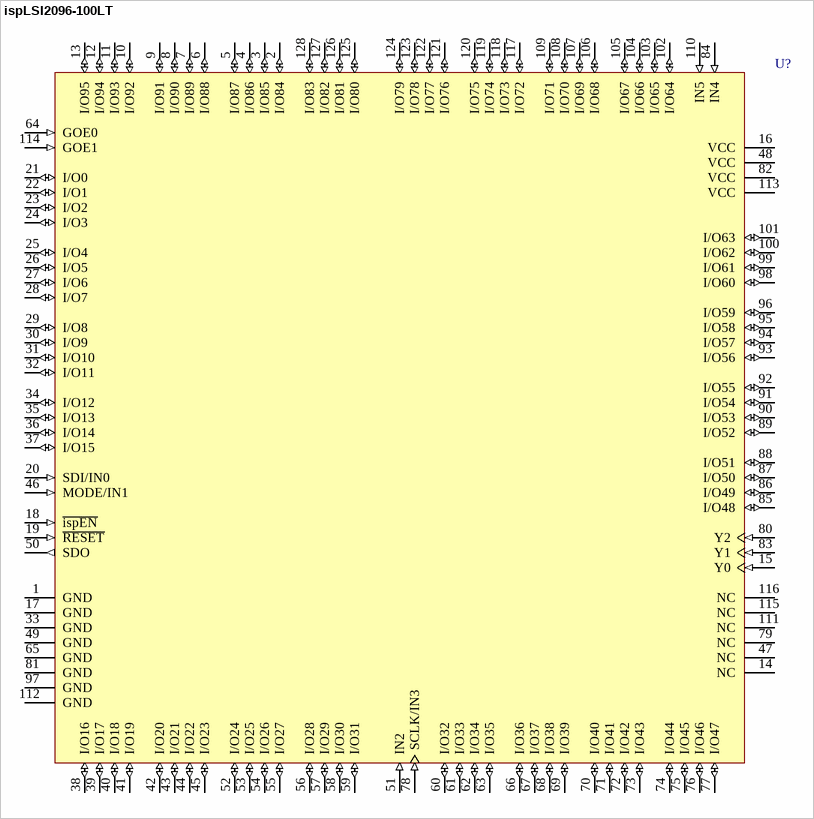
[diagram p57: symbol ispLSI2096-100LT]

## ispLSI2096-100LT
designator U?
In-System Programmable High-Density PLD; Note: Pins 20, 46 and 78 have dual function capability.
footprint TQFP128_N (Thin QFP, 128-Leads, Body 14x14mm, Pitch 0.4mm, IPC Medium Density)
footprint TQFP128_L (Thin QFP, 128-Leads, Body 14x14mm, Pitch 0.4mm, IPC High Density)
footprint TQFP128_M (Thin QFP, 128-Leads, Body 14x14mm, Pitch 0.4mm, IPC Low Density)
3D model 2096-TQFP128 (128-Pin Thin Quad Flat Pack 0.4 mm Pitch)
pins: 1 GND (power), 2 I/O84 (io), 3 I/O85 (io), 4 I/O86 (io), 5 I/O87 (io), 6 I/O88 (io), 7 I/O89 (io), 8 I/O90 (io), 9 I/O91 (io), 10 I/O92 (io), 11 I/O93 (io), 12 I/O94 (io), 13 I/O95 (io), 14 NC, 15 Y0 (in), 16 VCC (power), 17 GND (power), 18 ~{ispEN} (in), 19 ~{RESET} (in), 20 SDI/IN0 (in), 21 I/O0 (io), 22 I/O1 (io), 23 I/O2 (io), 24 I/O3 (io), 25 I/O4 (io), 26 I/O5 (io), 27 I/O6 (io), 28 I/O7 (io), 29 I/O8 (io), 30 I/O9 (io), 31 I/O10 (io), 32 I/O11 (io), 33 GND (power), 34 I/O12 (io), 35 I/O13 (io), 36 I/O14 (io), 37 I/O15 (io), 38 I/O16 (io), 39 I/O17 (io), 40 I/O18 (io), 41 I/O19 (io), 42 I/O20 (io), 43 I/O21 (io), 44 I/O22 (io), 45 I/O23 (io), 46 MODE/IN1 (in), 47 NC, 48 VCC (power), 49 GND (power), 50 SDO (out), 51 IN2 (in), 52 I/O24 (io), 53 I/O25 (io), 54 I/O26 (io), 55 I/O27 (io), 56 I/O28 (io), 57 I/O29 (io), 58 I/O30 (io), 59 I/O31 (io), 60 I/O32 (io), 61 I/O33 (io), 62 I/O34 (io), 63 I/O35 (io), 64 GOE0 (in), 65 GND (power), 66 I/O36 (io), 67 I/O37 (io), 68 I/O38 (io), 69 I/O39 (io), 70 I/O40 (io), 71 I/O41 (io), 72 I/O42 (io), 73 I/O43 (io), 74 I/O44 (io), 75 I/O45 (io), 76 I/O46 (io), 77 I/O47 (io), 78 SCLK/IN3 (in), 79 NC, 80 Y2 (in), 81 GND (power), 82 VCC (power), 83 Y1 (in), 84 IN4 (in), 85 I/O48 (io), 86 I/O49 (io), 87 I/O50 (io), 88 I/O51 (io), 89 I/O52 (io), 90 I/O53 (io), 91 I/O54 (io), 92 I/O55 (io), 93 I/O56 (io), 94 I/O57 (io), 95 I/O58 (io), 96 I/O59 (io), 97 GND (power), 98 I/O60 (io), 99 I/O61 (io), 100 I/O62 (io), 101 I/O63 (io), 102 I/O64 (io), 103 I/O65 (io), 104 I/O66 (io), 105 I/O67 (io), 106 I/O68 (io), 107 I/O69 (io), 108 I/O70 (io), 109 I/O71 (io), 110 IN5 (in), 111 NC, 112 GND (power), 113 VCC (power), 114 GOE1 (in), 115 NC, 116 NC, 117 I/O72 (io), 118 I/O73 (io), 119 I/O74 (io), 120 I/O75 (io), 121 I/O76 (io), 122 I/O77 (io), 123 I/O78 (io), 124 I/O79 (io), 125 I/O80 (io), 126 I/O81 (io), 127 I/O82 (io), 128 I/O83 (io)

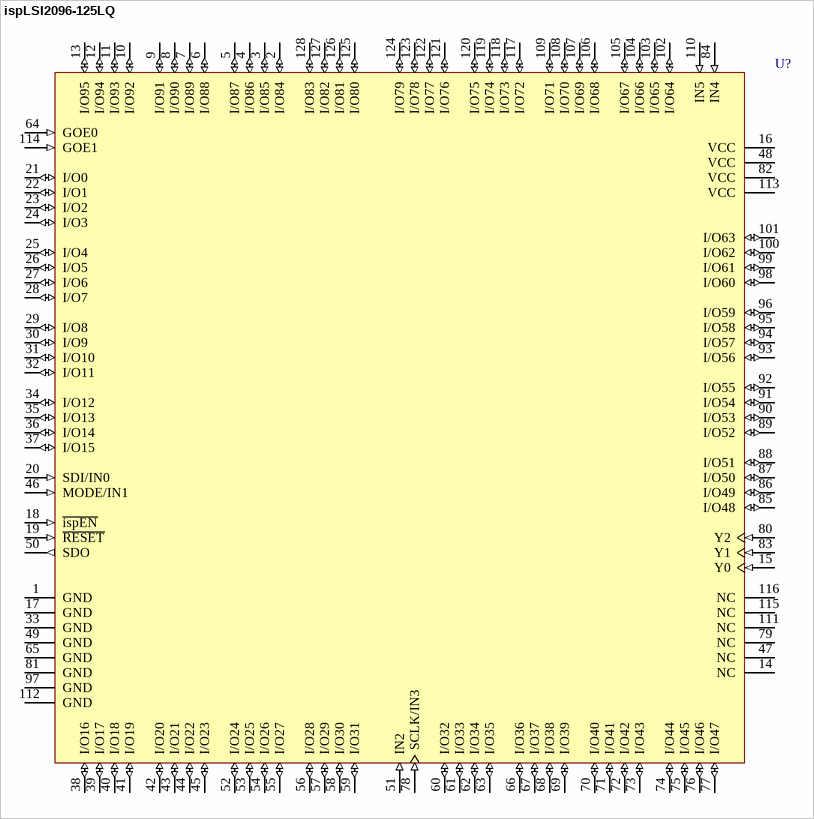
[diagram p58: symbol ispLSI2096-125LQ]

## ispLSI2096-125LQ
designator U?
In-System Programmable High-Density PLD; Note: Pins 20, 46 and 78 have dual function capability.
footprint PQFP128_N (QFP, 128-Leads, Body 28x28mm, Pitch 0.8mm, IPC Medium Density)
footprint PQFP128_L (QFP, 128-Leads, Body 28x28mm, Pitch 0.8mm, IPC High Density)
footprint PQFP128_M (QFP, 128-Leads, Body 28x28mm, Pitch 0.8mm, IPC Low Density)
3D model 2096-PQFP128 (128-Pin Quad Flat Pack 0.8 mm Pitch)
pins: 1 GND (power), 2 I/O84 (io), 3 I/O85 (io), 4 I/O86 (io), 5 I/O87 (io), 6 I/O88 (io), 7 I/O89 (io), 8 I/O90 (io), 9 I/O91 (io), 10 I/O92 (io), 11 I/O93 (io), 12 I/O94 (io), 13 I/O95 (io), 14 NC, 15 Y0 (in), 16 VCC (power), 17 GND (power), 18 ~{ispEN} (in), 19 ~{RESET} (in), 20 SDI/IN0 (in), 21 I/O0 (io), 22 I/O1 (io), 23 I/O2 (io), 24 I/O3 (io), 25 I/O4 (io), 26 I/O5 (io), 27 I/O6 (io), 28 I/O7 (io), 29 I/O8 (io), 30 I/O9 (io), 31 I/O10 (io), 32 I/O11 (io), 33 GND (power), 34 I/O12 (io), 35 I/O13 (io), 36 I/O14 (io), 37 I/O15 (io), 38 I/O16 (io), 39 I/O17 (io), 40 I/O18 (io), 41 I/O19 (io), 42 I/O20 (io), 43 I/O21 (io), 44 I/O22 (io), 45 I/O23 (io), 46 MODE/IN1 (in), 47 NC, 48 VCC (power), 49 GND (power), 50 SDO (out), 51 IN2 (in), 52 I/O24 (io), 53 I/O25 (io), 54 I/O26 (io), 55 I/O27 (io), 56 I/O28 (io), 57 I/O29 (io), 58 I/O30 (io), 59 I/O31 (io), 60 I/O32 (io), 61 I/O33 (io), 62 I/O34 (io), 63 I/O35 (io), 64 GOE0 (in), 65 GND (power), 66 I/O36 (io), 67 I/O37 (io), 68 I/O38 (io), 69 I/O39 (io), 70 I/O40 (io), 71 I/O41 (io), 72 I/O42 (io), 73 I/O43 (io), 74 I/O44 (io), 75 I/O45 (io), 76 I/O46 (io), 77 I/O47 (io), 78 SCLK/IN3 (in), 79 NC, 80 Y2 (in), 81 GND (power), 82 VCC (power), 83 Y1 (in), 84 IN4 (in), 85 I/O48 (io), 86 I/O49 (io), 87 I/O50 (io), 88 I/O51 (io), 89 I/O52 (io), 90 I/O53 (io), 91 I/O54 (io), 92 I/O55 (io), 93 I/O56 (io), 94 I/O57 (io), 95 I/O58 (io), 96 I/O59 (io), 97 GND (power), 98 I/O60 (io), 99 I/O61 (io), 100 I/O62 (io), 101 I/O63 (io), 102 I/O64 (io), 103 I/O65 (io), 104 I/O66 (io), 105 I/O67 (io), 106 I/O68 (io), 107 I/O69 (io), 108 I/O70 (io), 109 I/O71 (io), 110 IN5 (in), 111 NC, 112 GND (power), 113 VCC (power), 114 GOE1 (in), 115 NC, 116 NC, 117 I/O72 (io), 118 I/O73 (io), 119 I/O74 (io), 120 I/O75 (io), 121 I/O76 (io), 122 I/O77 (io), 123 I/O78 (io), 124 I/O79 (io), 125 I/O80 (io), 126 I/O81 (io), 127 I/O82 (io), 128 I/O83 (io)

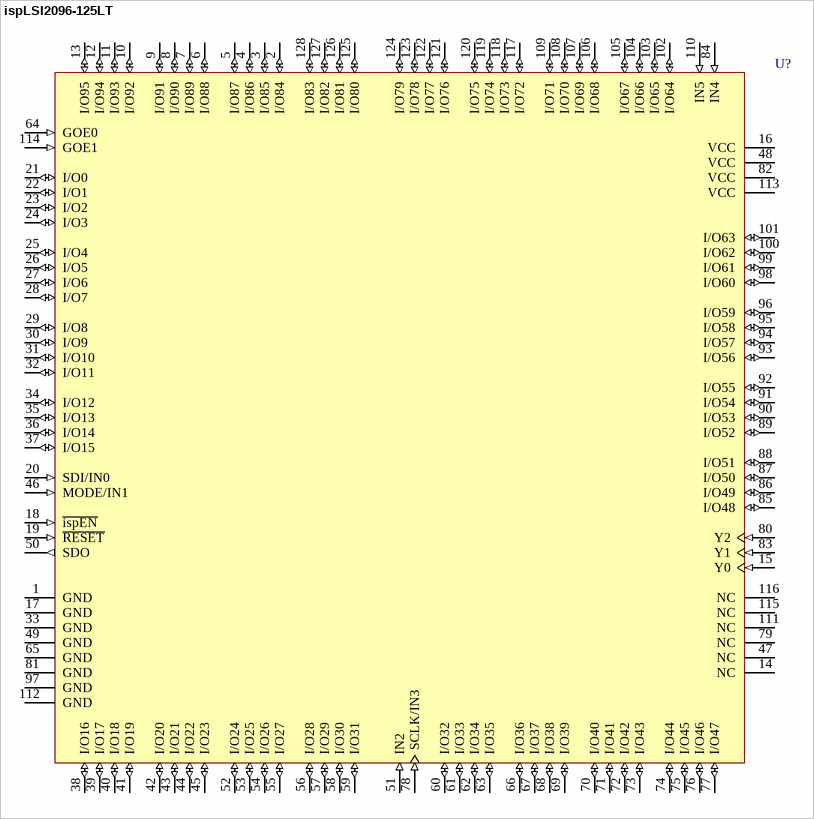
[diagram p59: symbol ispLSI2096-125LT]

## ispLSI2096-125LT
designator U?
In-System Programmable High-Density PLD; Note: Pins 20, 46 and 78 have dual function capability.
footprint TQFP128_N (Thin QFP, 128-Leads, Body 14x14mm, Pitch 0.4mm, IPC Medium Density)
footprint TQFP128_L (Thin QFP, 128-Leads, Body 14x14mm, Pitch 0.4mm, IPC High Density)
footprint TQFP128_M (Thin QFP, 128-Leads, Body 14x14mm, Pitch 0.4mm, IPC Low Density)
3D model 2096-TQFP128 (128-Pin Thin Quad Flat Pack 0.4 mm Pitch)
pins: 1 GND (power), 2 I/O84 (io), 3 I/O85 (io), 4 I/O86 (io), 5 I/O87 (io), 6 I/O88 (io), 7 I/O89 (io), 8 I/O90 (io), 9 I/O91 (io), 10 I/O92 (io), 11 I/O93 (io), 12 I/O94 (io), 13 I/O95 (io), 14 NC, 15 Y0 (in), 16 VCC (power), 17 GND (power), 18 ~{ispEN} (in), 19 ~{RESET} (in), 20 SDI/IN0 (in), 21 I/O0 (io), 22 I/O1 (io), 23 I/O2 (io), 24 I/O3 (io), 25 I/O4 (io), 26 I/O5 (io), 27 I/O6 (io), 28 I/O7 (io), 29 I/O8 (io), 30 I/O9 (io), 31 I/O10 (io), 32 I/O11 (io), 33 GND (power), 34 I/O12 (io), 35 I/O13 (io), 36 I/O14 (io), 37 I/O15 (io), 38 I/O16 (io), 39 I/O17 (io), 40 I/O18 (io), 41 I/O19 (io), 42 I/O20 (io), 43 I/O21 (io), 44 I/O22 (io), 45 I/O23 (io), 46 MODE/IN1 (in), 47 NC, 48 VCC (power), 49 GND (power), 50 SDO (out), 51 IN2 (in), 52 I/O24 (io), 53 I/O25 (io), 54 I/O26 (io), 55 I/O27 (io), 56 I/O28 (io), 57 I/O29 (io), 58 I/O30 (io), 59 I/O31 (io), 60 I/O32 (io), 61 I/O33 (io), 62 I/O34 (io), 63 I/O35 (io), 64 GOE0 (in), 65 GND (power), 66 I/O36 (io), 67 I/O37 (io), 68 I/O38 (io), 69 I/O39 (io), 70 I/O40 (io), 71 I/O41 (io), 72 I/O42 (io), 73 I/O43 (io), 74 I/O44 (io), 75 I/O45 (io), 76 I/O46 (io), 77 I/O47 (io), 78 SCLK/IN3 (in), 79 NC, 80 Y2 (in), 81 GND (power), 82 VCC (power), 83 Y1 (in), 84 IN4 (in), 85 I/O48 (io), 86 I/O49 (io), 87 I/O50 (io), 88 I/O51 (io), 89 I/O52 (io), 90 I/O53 (io), 91 I/O54 (io), 92 I/O55 (io), 93 I/O56 (io), 94 I/O57 (io), 95 I/O58 (io), 96 I/O59 (io), 97 GND (power), 98 I/O60 (io), 99 I/O61 (io), 100 I/O62 (io), 101 I/O63 (io), 102 I/O64 (io), 103 I/O65 (io), 104 I/O66 (io), 105 I/O67 (io), 106 I/O68 (io), 107 I/O69 (io), 108 I/O70 (io), 109 I/O71 (io), 110 IN5 (in), 111 NC, 112 GND (power), 113 VCC (power), 114 GOE1 (in), 115 NC, 116 NC, 117 I/O72 (io), 118 I/O73 (io), 119 I/O74 (io), 120 I/O75 (io), 121 I/O76 (io), 122 I/O77 (io), 123 I/O78 (io), 124 I/O79 (io), 125 I/O80 (io), 126 I/O81 (io), 127 I/O82 (io), 128 I/O83 (io)

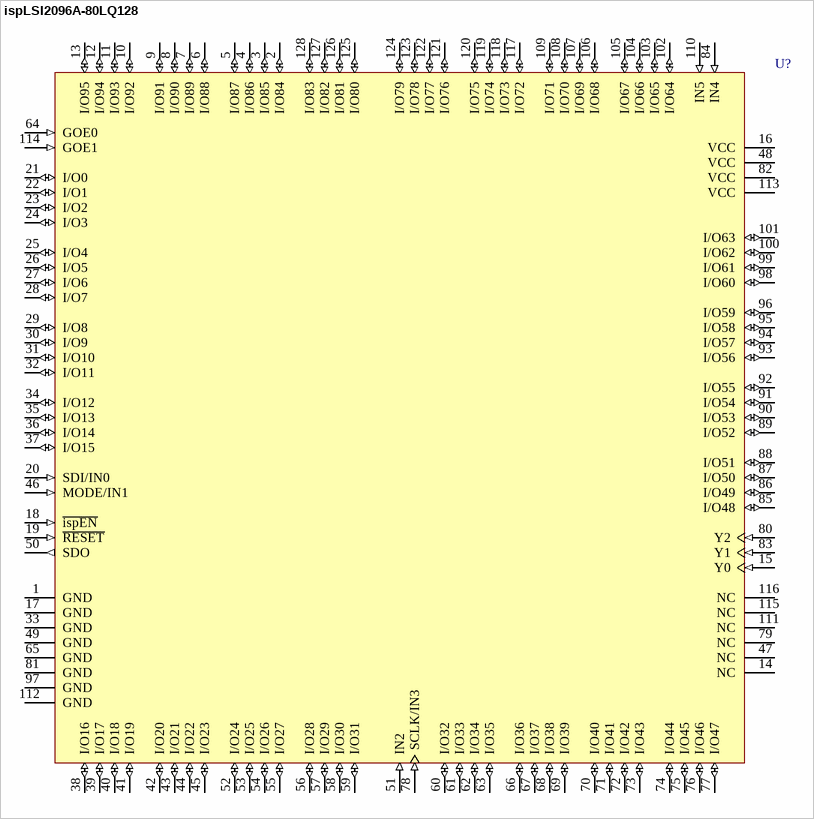
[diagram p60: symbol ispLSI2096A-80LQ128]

## ispLSI2096A-80LQ128
designator U?
In-System Programmable High-Density PLD; Note: Pins 20, 46 and 78 have dual function capability.
footprint PQFP128_N (QFP, 128-Leads, Body 28x28mm, Pitch 0.8mm, IPC Medium Density)
footprint PQFP128_L (QFP, 128-Leads, Body 28x28mm, Pitch 0.8mm, IPC High Density)
footprint PQFP128_M (QFP, 128-Leads, Body 28x28mm, Pitch 0.8mm, IPC Low Density)
3D model 2096A-PQFP128 (128-Pin Quad Flat Pack 0.8 mm Pitch)
pins: 1 GND (power), 2 I/O84 (io), 3 I/O85 (io), 4 I/O86 (io), 5 I/O87 (io), 6 I/O88 (io), 7 I/O89 (io), 8 I/O90 (io), 9 I/O91 (io), 10 I/O92 (io), 11 I/O93 (io), 12 I/O94 (io), 13 I/O95 (io), 14 NC, 15 Y0 (in), 16 VCC (power), 17 GND (power), 18 ~{ispEN} (in), 19 ~{RESET} (in), 20 SDI/IN0 (in), 21 I/O0 (io), 22 I/O1 (io), 23 I/O2 (io), 24 I/O3 (io), 25 I/O4 (io), 26 I/O5 (io), 27 I/O6 (io), 28 I/O7 (io), 29 I/O8 (io), 30 I/O9 (io), 31 I/O10 (io), 32 I/O11 (io), 33 GND (power), 34 I/O12 (io), 35 I/O13 (io), 36 I/O14 (io), 37 I/O15 (io), 38 I/O16 (io), 39 I/O17 (io), 40 I/O18 (io), 41 I/O19 (io), 42 I/O20 (io), 43 I/O21 (io), 44 I/O22 (io), 45 I/O23 (io), 46 MODE/IN1 (in), 47 NC, 48 VCC (power), 49 GND (power), 50 SDO (out), 51 IN2 (in), 52 I/O24 (io), 53 I/O25 (io), 54 I/O26 (io), 55 I/O27 (io), 56 I/O28 (io), 57 I/O29 (io), 58 I/O30 (io), 59 I/O31 (io), 60 I/O32 (io), 61 I/O33 (io), 62 I/O34 (io), 63 I/O35 (io), 64 GOE0 (in), 65 GND (power), 66 I/O36 (io), 67 I/O37 (io), 68 I/O38 (io), 69 I/O39 (io), 70 I/O40 (io), 71 I/O41 (io), 72 I/O42 (io), 73 I/O43 (io), 74 I/O44 (io), 75 I/O45 (io), 76 I/O46 (io), 77 I/O47 (io), 78 SCLK/IN3 (in), 79 NC, 80 Y2 (in), 81 GND (power), 82 VCC (power), 83 Y1 (in), 84 IN4 (in), 85 I/O48 (io), 86 I/O49 (io), 87 I/O50 (io), 88 I/O51 (io), 89 I/O52 (io), 90 I/O53 (io), 91 I/O54 (io), 92 I/O55 (io), 93 I/O56 (io), 94 I/O57 (io), 95 I/O58 (io), 96 I/O59 (io), 97 GND (power), 98 I/O60 (io), 99 I/O61 (io), 100 I/O62 (io), 101 I/O63 (io), 102 I/O64 (io), 103 I/O65 (io), 104 I/O66 (io), 105 I/O67 (io), 106 I/O68 (io), 107 I/O69 (io), 108 I/O70 (io), 109 I/O71 (io), 110 IN5 (in), 111 NC, 112 GND (power), 113 VCC (power), 114 GOE1 (in), 115 NC, 116 NC, 117 I/O72 (io), 118 I/O73 (io), 119 I/O74 (io), 120 I/O75 (io), 121 I/O76 (io), 122 I/O77 (io), 123 I/O78 (io), 124 I/O79 (io), 125 I/O80 (io), 126 I/O81 (io), 127 I/O82 (io), 128 I/O83 (io)

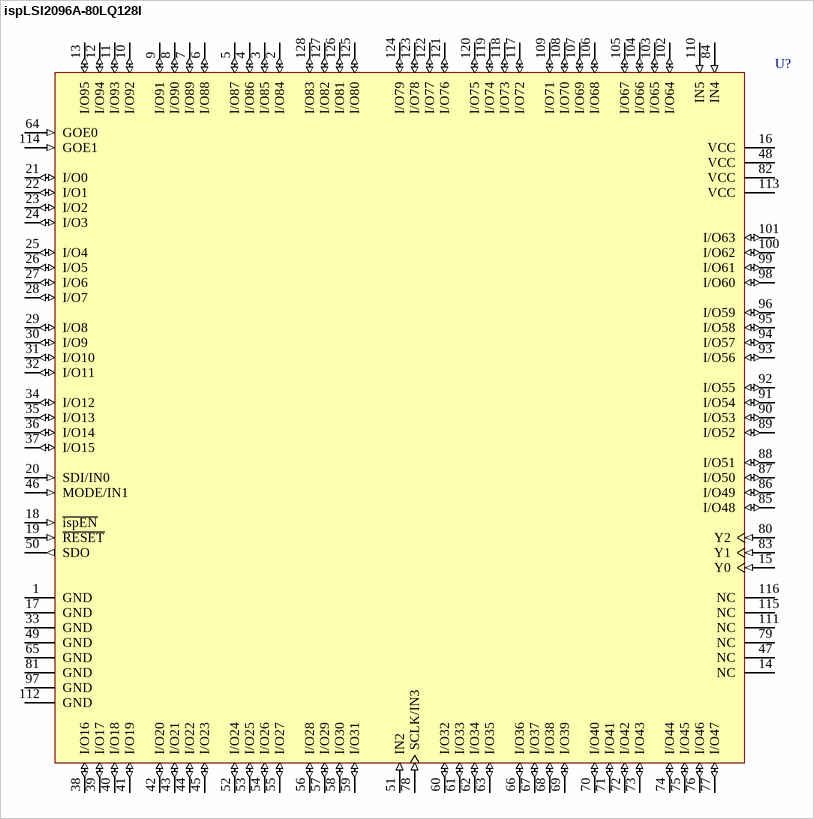
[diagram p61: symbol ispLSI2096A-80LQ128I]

## ispLSI2096A-80LQ128I
designator U?
In-System Programmable High-Density PLD; Note: Pins 20, 46 and 78 have dual function capability.
footprint PQFP128_N (QFP, 128-Leads, Body 28x28mm, Pitch 0.8mm, IPC Medium Density)
footprint PQFP128_L (QFP, 128-Leads, Body 28x28mm, Pitch 0.8mm, IPC High Density)
footprint PQFP128_M (QFP, 128-Leads, Body 28x28mm, Pitch 0.8mm, IPC Low Density)
3D model 2096A-PQFP128 (128-Pin Quad Flat Pack 0.8 mm Pitch)
pins: 1 GND (power), 2 I/O84 (io), 3 I/O85 (io), 4 I/O86 (io), 5 I/O87 (io), 6 I/O88 (io), 7 I/O89 (io), 8 I/O90 (io), 9 I/O91 (io), 10 I/O92 (io), 11 I/O93 (io), 12 I/O94 (io), 13 I/O95 (io), 14 NC, 15 Y0 (in), 16 VCC (power), 17 GND (power), 18 ~{ispEN} (in), 19 ~{RESET} (in), 20 SDI/IN0 (in), 21 I/O0 (io), 22 I/O1 (io), 23 I/O2 (io), 24 I/O3 (io), 25 I/O4 (io), 26 I/O5 (io), 27 I/O6 (io), 28 I/O7 (io), 29 I/O8 (io), 30 I/O9 (io), 31 I/O10 (io), 32 I/O11 (io), 33 GND (power), 34 I/O12 (io), 35 I/O13 (io), 36 I/O14 (io), 37 I/O15 (io), 38 I/O16 (io), 39 I/O17 (io), 40 I/O18 (io), 41 I/O19 (io), 42 I/O20 (io), 43 I/O21 (io), 44 I/O22 (io), 45 I/O23 (io), 46 MODE/IN1 (in), 47 NC, 48 VCC (power), 49 GND (power), 50 SDO (out), 51 IN2 (in), 52 I/O24 (io), 53 I/O25 (io), 54 I/O26 (io), 55 I/O27 (io), 56 I/O28 (io), 57 I/O29 (io), 58 I/O30 (io), 59 I/O31 (io), 60 I/O32 (io), 61 I/O33 (io), 62 I/O34 (io), 63 I/O35 (io), 64 GOE0 (in), 65 GND (power), 66 I/O36 (io), 67 I/O37 (io), 68 I/O38 (io), 69 I/O39 (io), 70 I/O40 (io), 71 I/O41 (io), 72 I/O42 (io), 73 I/O43 (io), 74 I/O44 (io), 75 I/O45 (io), 76 I/O46 (io), 77 I/O47 (io), 78 SCLK/IN3 (in), 79 NC, 80 Y2 (in), 81 GND (power), 82 VCC (power), 83 Y1 (in), 84 IN4 (in), 85 I/O48 (io), 86 I/O49 (io), 87 I/O50 (io), 88 I/O51 (io), 89 I/O52 (io), 90 I/O53 (io), 91 I/O54 (io), 92 I/O55 (io), 93 I/O56 (io), 94 I/O57 (io), 95 I/O58 (io), 96 I/O59 (io), 97 GND (power), 98 I/O60 (io), 99 I/O61 (io), 100 I/O62 (io), 101 I/O63 (io), 102 I/O64 (io), 103 I/O65 (io), 104 I/O66 (io), 105 I/O67 (io), 106 I/O68 (io), 107 I/O69 (io), 108 I/O70 (io), 109 I/O71 (io), 110 IN5 (in), 111 NC, 112 GND (power), 113 VCC (power), 114 GOE1 (in), 115 NC, 116 NC, 117 I/O72 (io), 118 I/O73 (io), 119 I/O74 (io), 120 I/O75 (io), 121 I/O76 (io), 122 I/O77 (io), 123 I/O78 (io), 124 I/O79 (io), 125 I/O80 (io), 126 I/O81 (io), 127 I/O82 (io), 128 I/O83 (io)

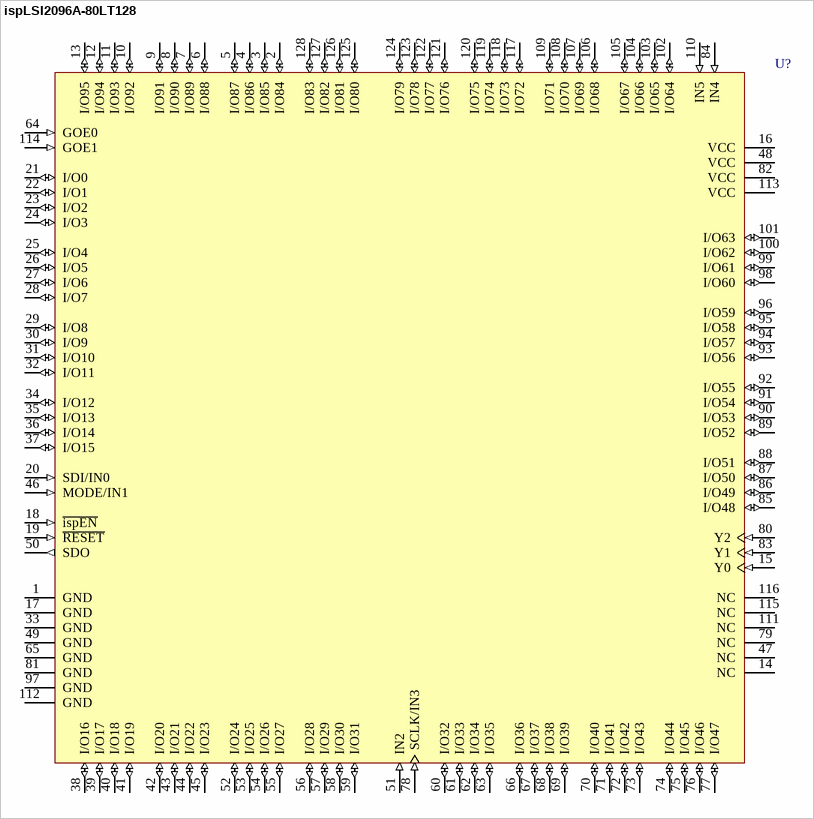
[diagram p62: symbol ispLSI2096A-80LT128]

## ispLSI2096A-80LT128
designator U?
In-System Programmable High-Density PLD; Note: Pins 20, 46 and 78 have dual function capability.
footprint TQFP128_N (Thin QFP, 128-Leads, Body 14x14mm, Pitch 0.4mm, IPC Medium Density)
footprint TQFP128_L (Thin QFP, 128-Leads, Body 14x14mm, Pitch 0.4mm, IPC High Density)
footprint TQFP128_M (Thin QFP, 128-Leads, Body 14x14mm, Pitch 0.4mm, IPC Low Density)
3D model 2096A-TQFP128 (128-Pin Thin Quad Flat Pack 0.4 mm Pitch)
pins: 1 GND (power), 2 I/O84 (io), 3 I/O85 (io), 4 I/O86 (io), 5 I/O87 (io), 6 I/O88 (io), 7 I/O89 (io), 8 I/O90 (io), 9 I/O91 (io), 10 I/O92 (io), 11 I/O93 (io), 12 I/O94 (io), 13 I/O95 (io), 14 NC, 15 Y0 (in), 16 VCC (power), 17 GND (power), 18 ~{ispEN} (in), 19 ~{RESET} (in), 20 SDI/IN0 (in), 21 I/O0 (io), 22 I/O1 (io), 23 I/O2 (io), 24 I/O3 (io), 25 I/O4 (io), 26 I/O5 (io), 27 I/O6 (io), 28 I/O7 (io), 29 I/O8 (io), 30 I/O9 (io), 31 I/O10 (io), 32 I/O11 (io), 33 GND (power), 34 I/O12 (io), 35 I/O13 (io), 36 I/O14 (io), 37 I/O15 (io), 38 I/O16 (io), 39 I/O17 (io), 40 I/O18 (io), 41 I/O19 (io), 42 I/O20 (io), 43 I/O21 (io), 44 I/O22 (io), 45 I/O23 (io), 46 MODE/IN1 (in), 47 NC, 48 VCC (power), 49 GND (power), 50 SDO (out), 51 IN2 (in), 52 I/O24 (io), 53 I/O25 (io), 54 I/O26 (io), 55 I/O27 (io), 56 I/O28 (io), 57 I/O29 (io), 58 I/O30 (io), 59 I/O31 (io), 60 I/O32 (io), 61 I/O33 (io), 62 I/O34 (io), 63 I/O35 (io), 64 GOE0 (in), 65 GND (power), 66 I/O36 (io), 67 I/O37 (io), 68 I/O38 (io), 69 I/O39 (io), 70 I/O40 (io), 71 I/O41 (io), 72 I/O42 (io), 73 I/O43 (io), 74 I/O44 (io), 75 I/O45 (io), 76 I/O46 (io), 77 I/O47 (io), 78 SCLK/IN3 (in), 79 NC, 80 Y2 (in), 81 GND (power), 82 VCC (power), 83 Y1 (in), 84 IN4 (in), 85 I/O48 (io), 86 I/O49 (io), 87 I/O50 (io), 88 I/O51 (io), 89 I/O52 (io), 90 I/O53 (io), 91 I/O54 (io), 92 I/O55 (io), 93 I/O56 (io), 94 I/O57 (io), 95 I/O58 (io), 96 I/O59 (io), 97 GND (power), 98 I/O60 (io), 99 I/O61 (io), 100 I/O62 (io), 101 I/O63 (io), 102 I/O64 (io), 103 I/O65 (io), 104 I/O66 (io), 105 I/O67 (io), 106 I/O68 (io), 107 I/O69 (io), 108 I/O70 (io), 109 I/O71 (io), 110 IN5 (in), 111 NC, 112 GND (power), 113 VCC (power), 114 GOE1 (in), 115 NC, 116 NC, 117 I/O72 (io), 118 I/O73 (io), 119 I/O74 (io), 120 I/O75 (io), 121 I/O76 (io), 122 I/O77 (io), 123 I/O78 (io), 124 I/O79 (io), 125 I/O80 (io), 126 I/O81 (io), 127 I/O82 (io), 128 I/O83 (io)

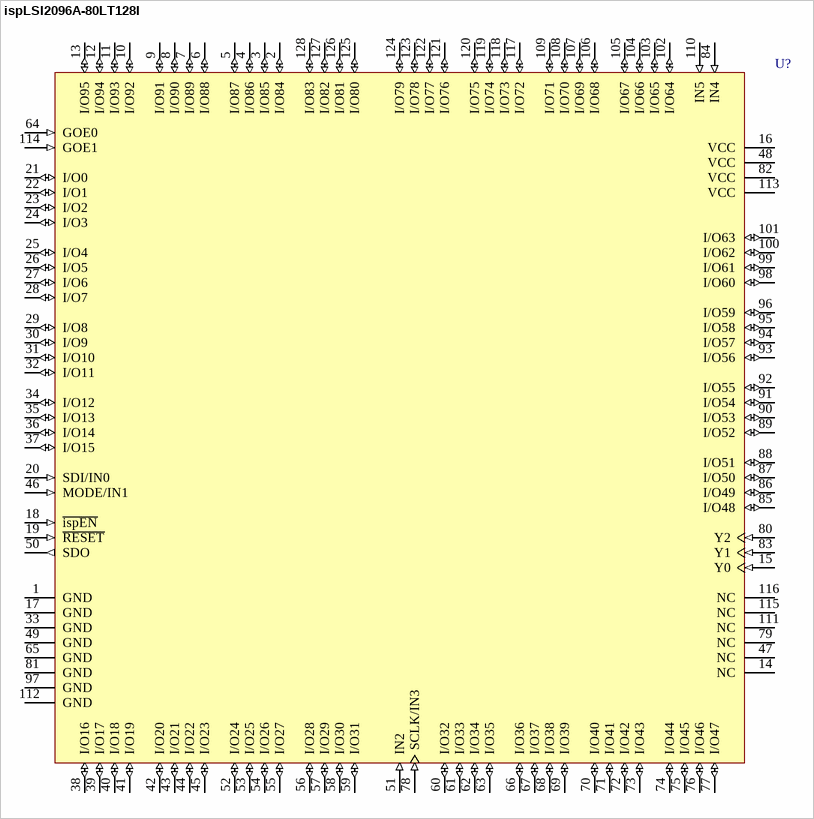
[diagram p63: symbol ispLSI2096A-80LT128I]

## ispLSI2096A-80LT128I
designator U?
In-System Programmable High-Density PLD; Note: Pins 20, 46 and 78 have dual function capability.
footprint TQFP128_N (Thin QFP, 128-Leads, Body 14x14mm, Pitch 0.4mm, IPC Medium Density)
footprint TQFP128_L (Thin QFP, 128-Leads, Body 14x14mm, Pitch 0.4mm, IPC High Density)
footprint TQFP128_M (Thin QFP, 128-Leads, Body 14x14mm, Pitch 0.4mm, IPC Low Density)
3D model 2096A-TQFP128 (128-Pin Thin Quad Flat Pack 0.4 mm Pitch)
pins: 1 GND (power), 2 I/O84 (io), 3 I/O85 (io), 4 I/O86 (io), 5 I/O87 (io), 6 I/O88 (io), 7 I/O89 (io), 8 I/O90 (io), 9 I/O91 (io), 10 I/O92 (io), 11 I/O93 (io), 12 I/O94 (io), 13 I/O95 (io), 14 NC, 15 Y0 (in), 16 VCC (power), 17 GND (power), 18 ~{ispEN} (in), 19 ~{RESET} (in), 20 SDI/IN0 (in), 21 I/O0 (io), 22 I/O1 (io), 23 I/O2 (io), 24 I/O3 (io), 25 I/O4 (io), 26 I/O5 (io), 27 I/O6 (io), 28 I/O7 (io), 29 I/O8 (io), 30 I/O9 (io), 31 I/O10 (io), 32 I/O11 (io), 33 GND (power), 34 I/O12 (io), 35 I/O13 (io), 36 I/O14 (io), 37 I/O15 (io), 38 I/O16 (io), 39 I/O17 (io), 40 I/O18 (io), 41 I/O19 (io), 42 I/O20 (io), 43 I/O21 (io), 44 I/O22 (io), 45 I/O23 (io), 46 MODE/IN1 (in), 47 NC, 48 VCC (power), 49 GND (power), 50 SDO (out), 51 IN2 (in), 52 I/O24 (io), 53 I/O25 (io), 54 I/O26 (io), 55 I/O27 (io), 56 I/O28 (io), 57 I/O29 (io), 58 I/O30 (io), 59 I/O31 (io), 60 I/O32 (io), 61 I/O33 (io), 62 I/O34 (io), 63 I/O35 (io), 64 GOE0 (in), 65 GND (power), 66 I/O36 (io), 67 I/O37 (io), 68 I/O38 (io), 69 I/O39 (io), 70 I/O40 (io), 71 I/O41 (io), 72 I/O42 (io), 73 I/O43 (io), 74 I/O44 (io), 75 I/O45 (io), 76 I/O46 (io), 77 I/O47 (io), 78 SCLK/IN3 (in), 79 NC, 80 Y2 (in), 81 GND (power), 82 VCC (power), 83 Y1 (in), 84 IN4 (in), 85 I/O48 (io), 86 I/O49 (io), 87 I/O50 (io), 88 I/O51 (io), 89 I/O52 (io), 90 I/O53 (io), 91 I/O54 (io), 92 I/O55 (io), 93 I/O56 (io), 94 I/O57 (io), 95 I/O58 (io), 96 I/O59 (io), 97 GND (power), 98 I/O60 (io), 99 I/O61 (io), 100 I/O62 (io), 101 I/O63 (io), 102 I/O64 (io), 103 I/O65 (io), 104 I/O66 (io), 105 I/O67 (io), 106 I/O68 (io), 107 I/O69 (io), 108 I/O70 (io), 109 I/O71 (io), 110 IN5 (in), 111 NC, 112 GND (power), 113 VCC (power), 114 GOE1 (in), 115 NC, 116 NC, 117 I/O72 (io), 118 I/O73 (io), 119 I/O74 (io), 120 I/O75 (io), 121 I/O76 (io), 122 I/O77 (io), 123 I/O78 (io), 124 I/O79 (io), 125 I/O80 (io), 126 I/O81 (io), 127 I/O82 (io), 128 I/O83 (io)

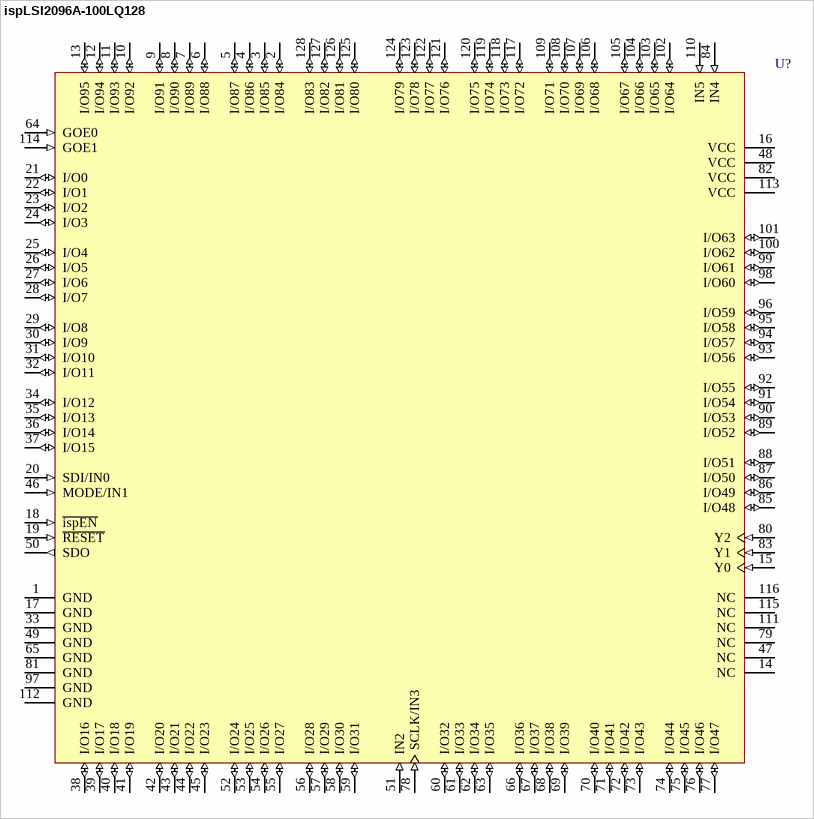
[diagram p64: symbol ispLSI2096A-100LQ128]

## ispLSI2096A-100LQ128
designator U?
In-System Programmable High-Density PLD; Note: Pins 20, 46 and 78 have dual function capability.
footprint PQFP128_N (QFP, 128-Leads, Body 28x28mm, Pitch 0.8mm, IPC Medium Density)
footprint PQFP128_L (QFP, 128-Leads, Body 28x28mm, Pitch 0.8mm, IPC High Density)
footprint PQFP128_M (QFP, 128-Leads, Body 28x28mm, Pitch 0.8mm, IPC Low Density)
3D model 2096A-PQFP128 (128-Pin Quad Flat Pack 0.8 mm Pitch)
pins: 1 GND (power), 2 I/O84 (io), 3 I/O85 (io), 4 I/O86 (io), 5 I/O87 (io), 6 I/O88 (io), 7 I/O89 (io), 8 I/O90 (io), 9 I/O91 (io), 10 I/O92 (io), 11 I/O93 (io), 12 I/O94 (io), 13 I/O95 (io), 14 NC, 15 Y0 (in), 16 VCC (power), 17 GND (power), 18 ~{ispEN} (in), 19 ~{RESET} (in), 20 SDI/IN0 (in), 21 I/O0 (io), 22 I/O1 (io), 23 I/O2 (io), 24 I/O3 (io), 25 I/O4 (io), 26 I/O5 (io), 27 I/O6 (io), 28 I/O7 (io), 29 I/O8 (io), 30 I/O9 (io), 31 I/O10 (io), 32 I/O11 (io), 33 GND (power), 34 I/O12 (io), 35 I/O13 (io), 36 I/O14 (io), 37 I/O15 (io), 38 I/O16 (io), 39 I/O17 (io), 40 I/O18 (io), 41 I/O19 (io), 42 I/O20 (io), 43 I/O21 (io), 44 I/O22 (io), 45 I/O23 (io), 46 MODE/IN1 (in), 47 NC, 48 VCC (power), 49 GND (power), 50 SDO (out), 51 IN2 (in), 52 I/O24 (io), 53 I/O25 (io), 54 I/O26 (io), 55 I/O27 (io), 56 I/O28 (io), 57 I/O29 (io), 58 I/O30 (io), 59 I/O31 (io), 60 I/O32 (io), 61 I/O33 (io), 62 I/O34 (io), 63 I/O35 (io), 64 GOE0 (in), 65 GND (power), 66 I/O36 (io), 67 I/O37 (io), 68 I/O38 (io), 69 I/O39 (io), 70 I/O40 (io), 71 I/O41 (io), 72 I/O42 (io), 73 I/O43 (io), 74 I/O44 (io), 75 I/O45 (io), 76 I/O46 (io), 77 I/O47 (io), 78 SCLK/IN3 (in), 79 NC, 80 Y2 (in), 81 GND (power), 82 VCC (power), 83 Y1 (in), 84 IN4 (in), 85 I/O48 (io), 86 I/O49 (io), 87 I/O50 (io), 88 I/O51 (io), 89 I/O52 (io), 90 I/O53 (io), 91 I/O54 (io), 92 I/O55 (io), 93 I/O56 (io), 94 I/O57 (io), 95 I/O58 (io), 96 I/O59 (io), 97 GND (power), 98 I/O60 (io), 99 I/O61 (io), 100 I/O62 (io), 101 I/O63 (io), 102 I/O64 (io), 103 I/O65 (io), 104 I/O66 (io), 105 I/O67 (io), 106 I/O68 (io), 107 I/O69 (io), 108 I/O70 (io), 109 I/O71 (io), 110 IN5 (in), 111 NC, 112 GND (power), 113 VCC (power), 114 GOE1 (in), 115 NC, 116 NC, 117 I/O72 (io), 118 I/O73 (io), 119 I/O74 (io), 120 I/O75 (io), 121 I/O76 (io), 122 I/O77 (io), 123 I/O78 (io), 124 I/O79 (io), 125 I/O80 (io), 126 I/O81 (io), 127 I/O82 (io), 128 I/O83 (io)

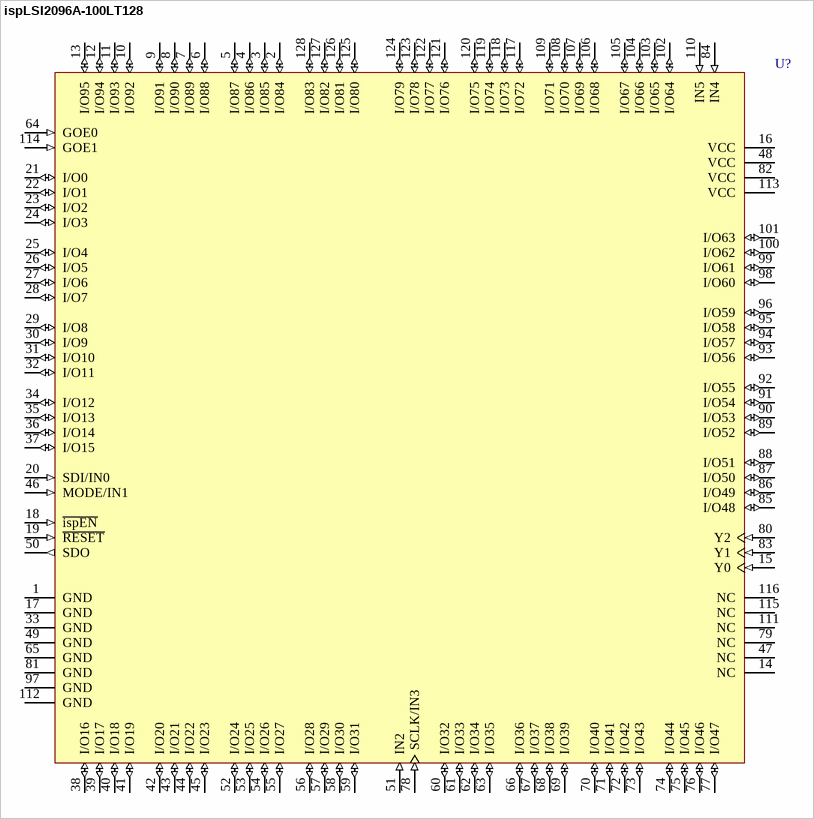
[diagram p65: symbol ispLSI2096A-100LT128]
